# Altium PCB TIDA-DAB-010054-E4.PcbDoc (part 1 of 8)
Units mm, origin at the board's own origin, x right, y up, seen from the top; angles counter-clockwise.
Board outline 300 x 180 mm, 4 copper layers (Top Layer, Inner Layer1, Inner Layer2, Bottom Layer), stack 1.605 mm thick; 873 components, 388 nets, 2405 pads, 1542 vias.
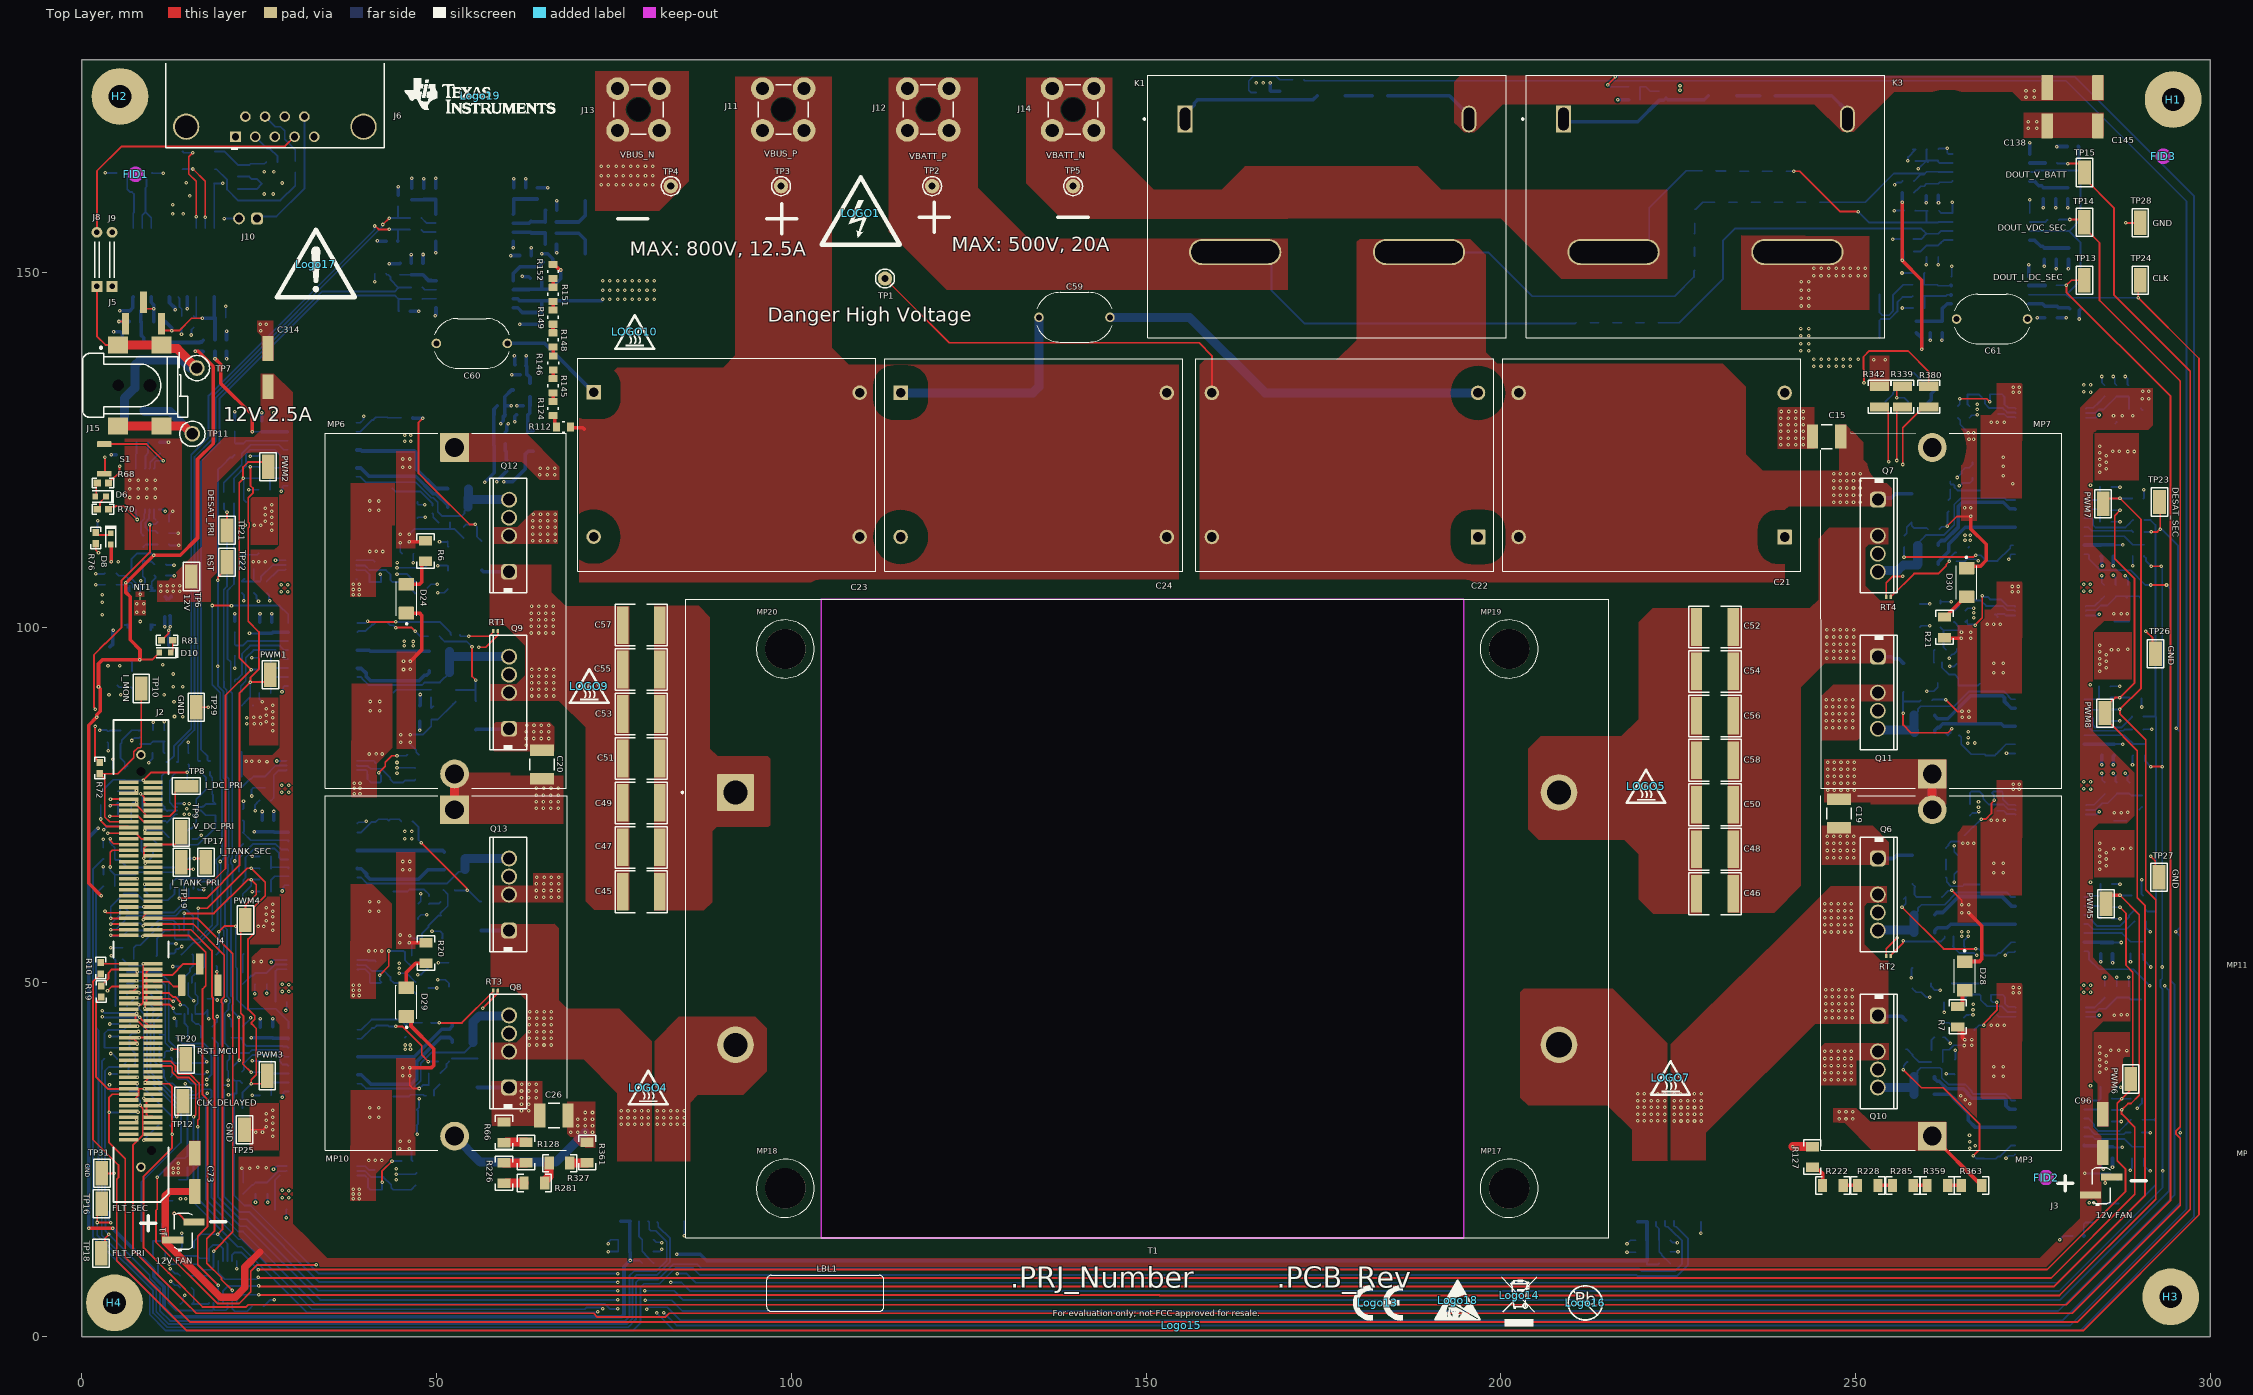
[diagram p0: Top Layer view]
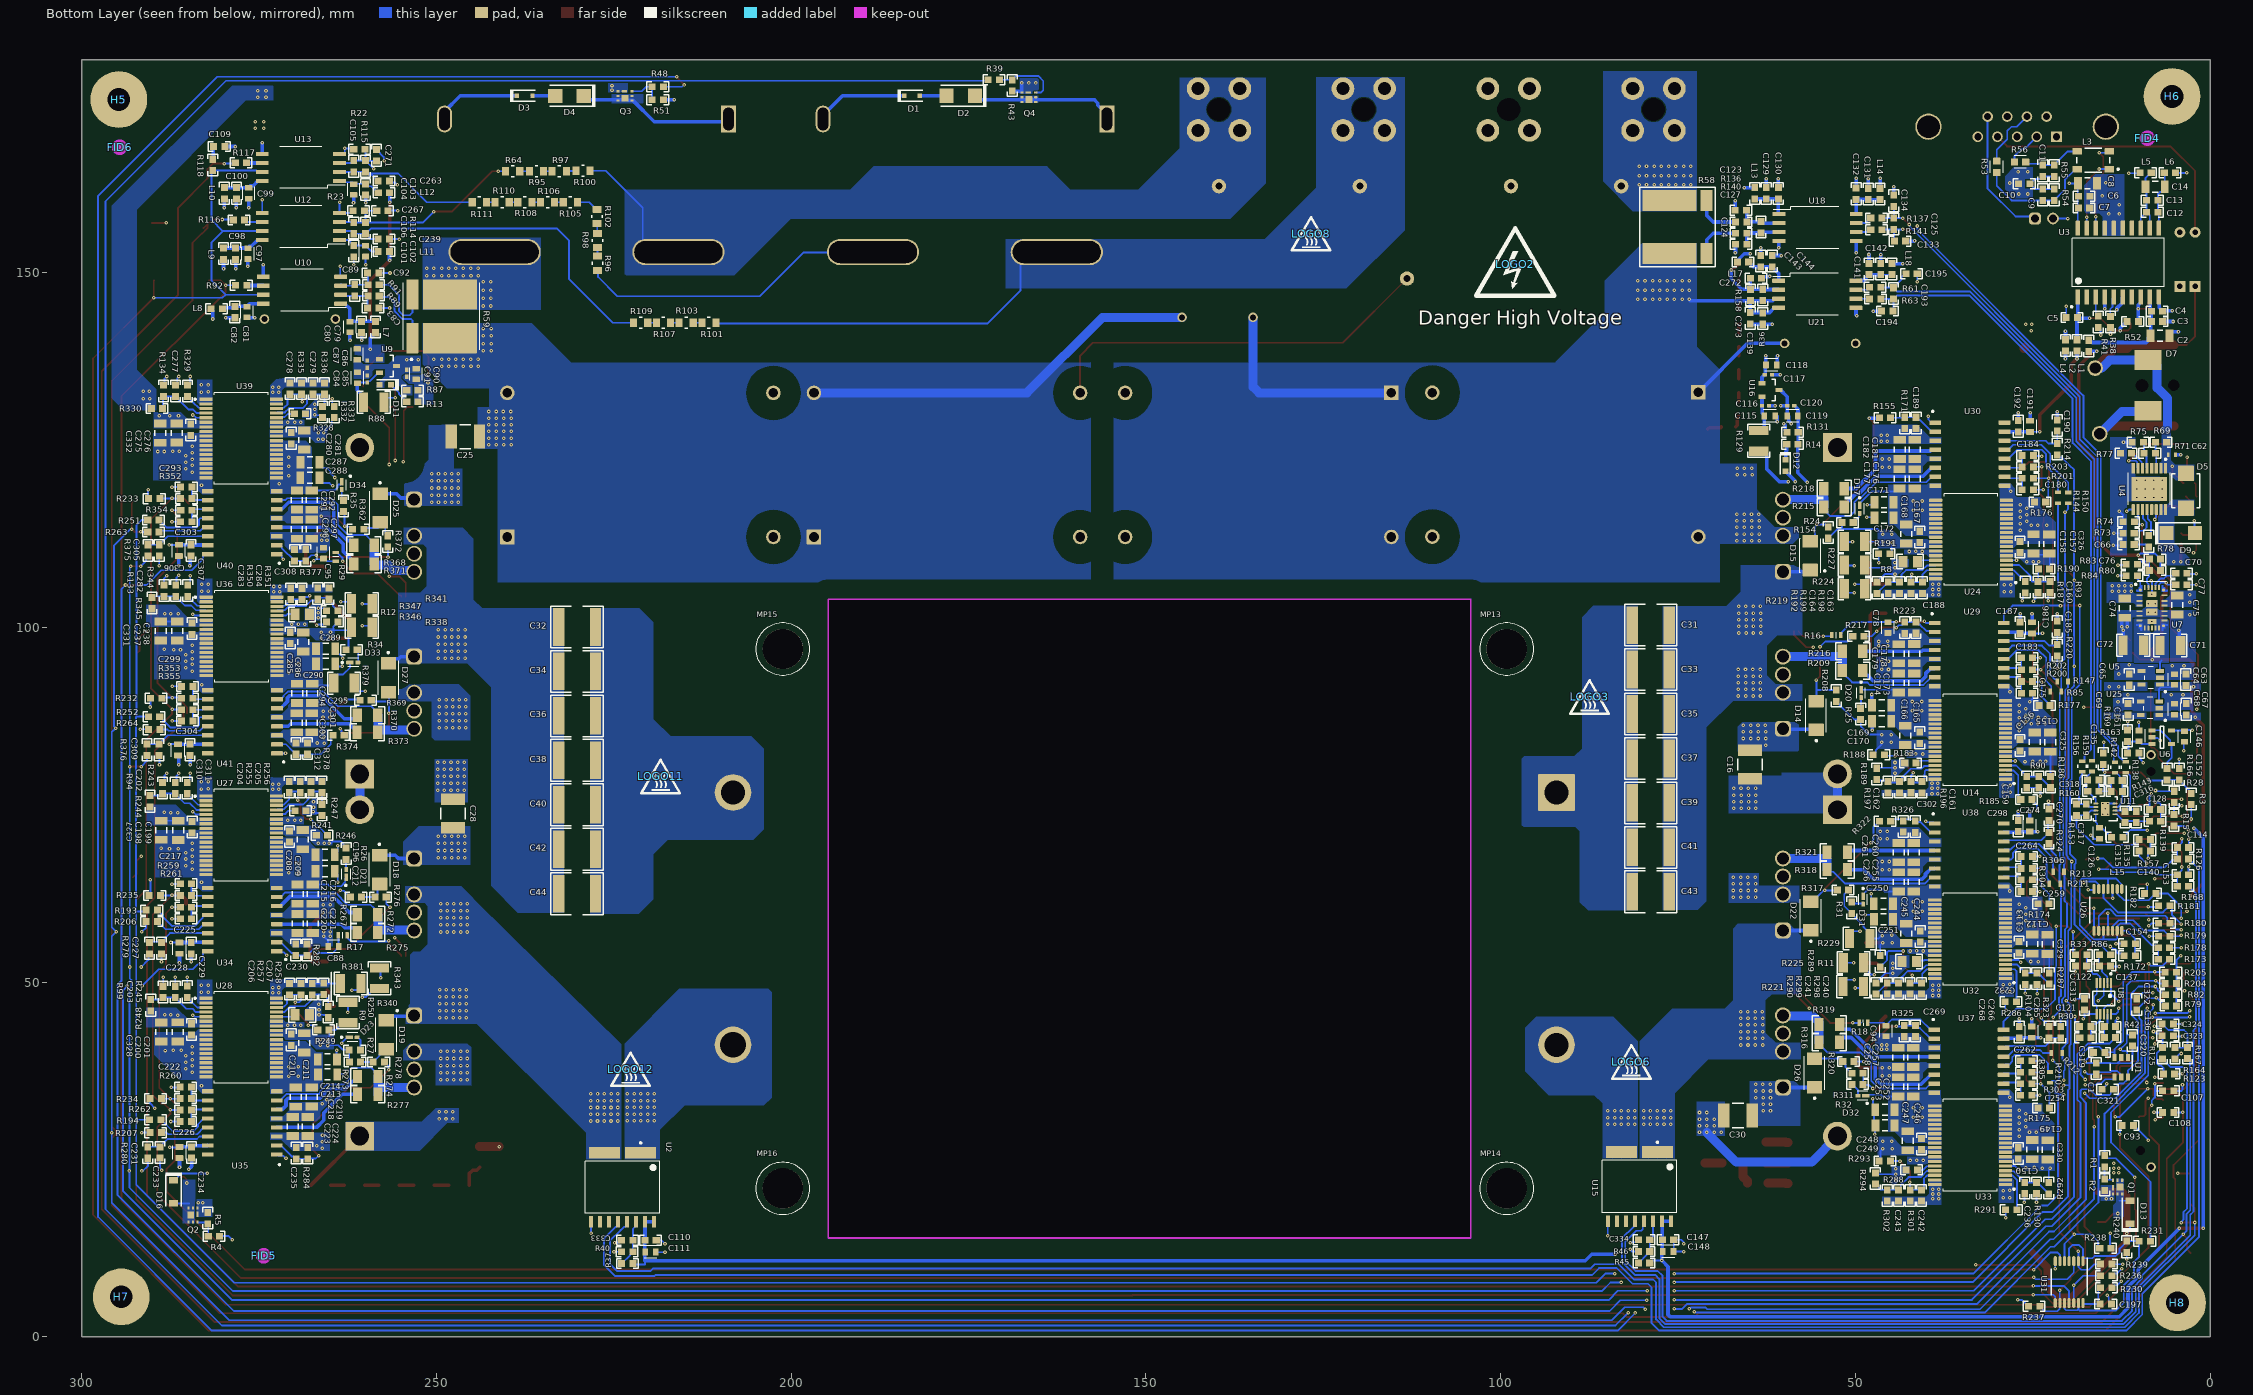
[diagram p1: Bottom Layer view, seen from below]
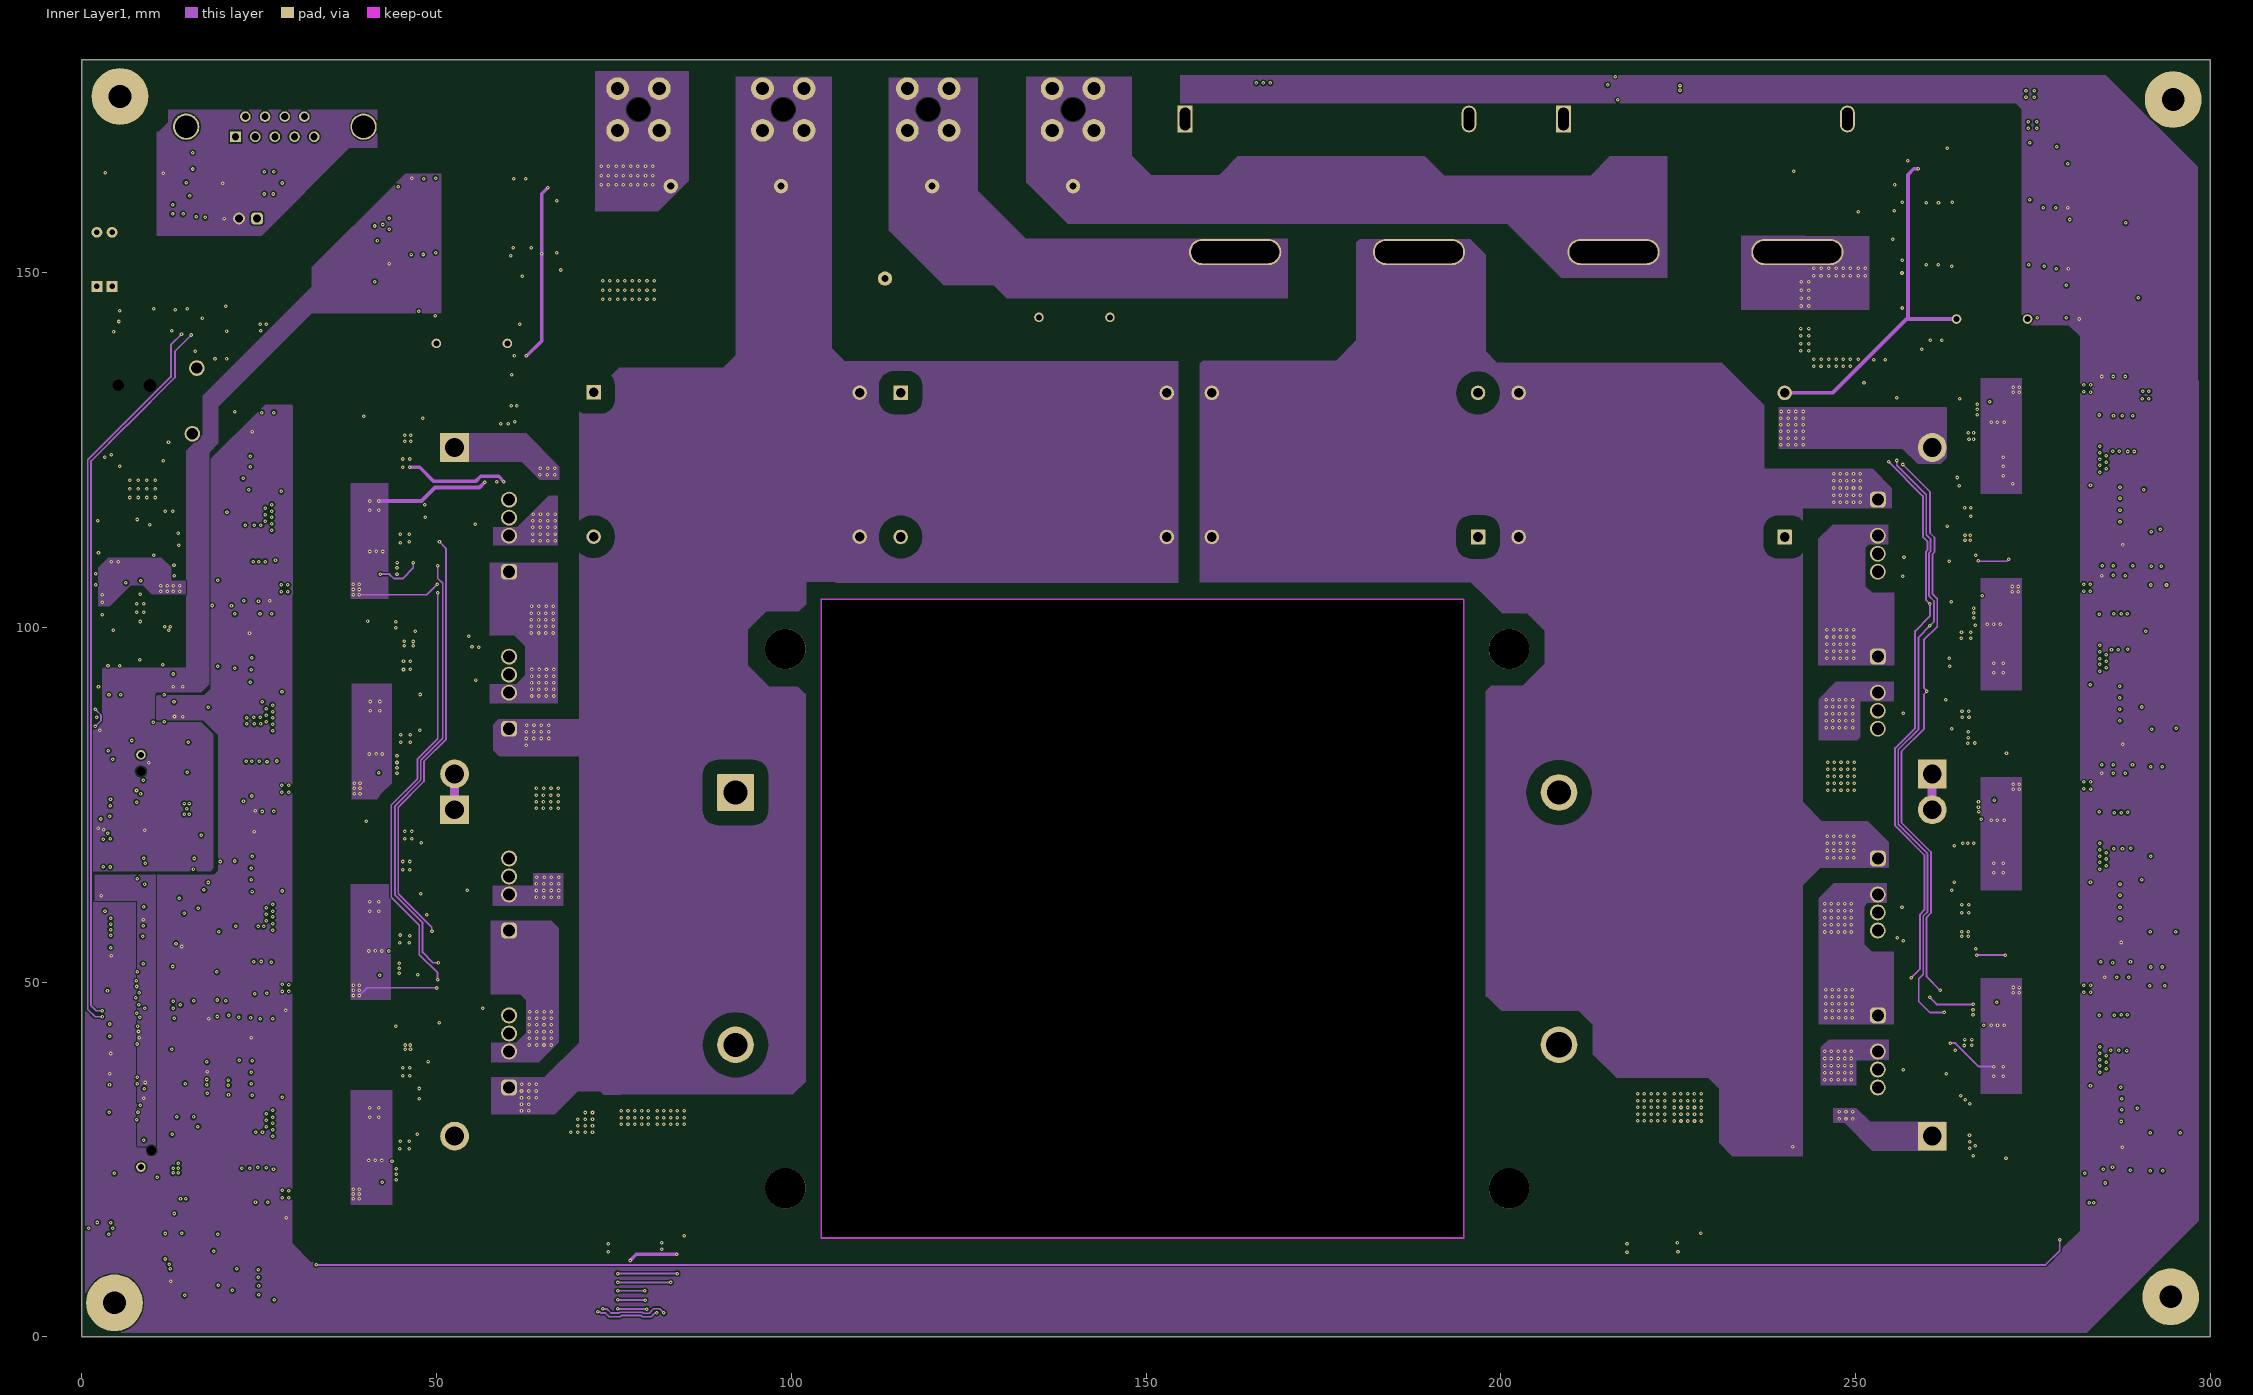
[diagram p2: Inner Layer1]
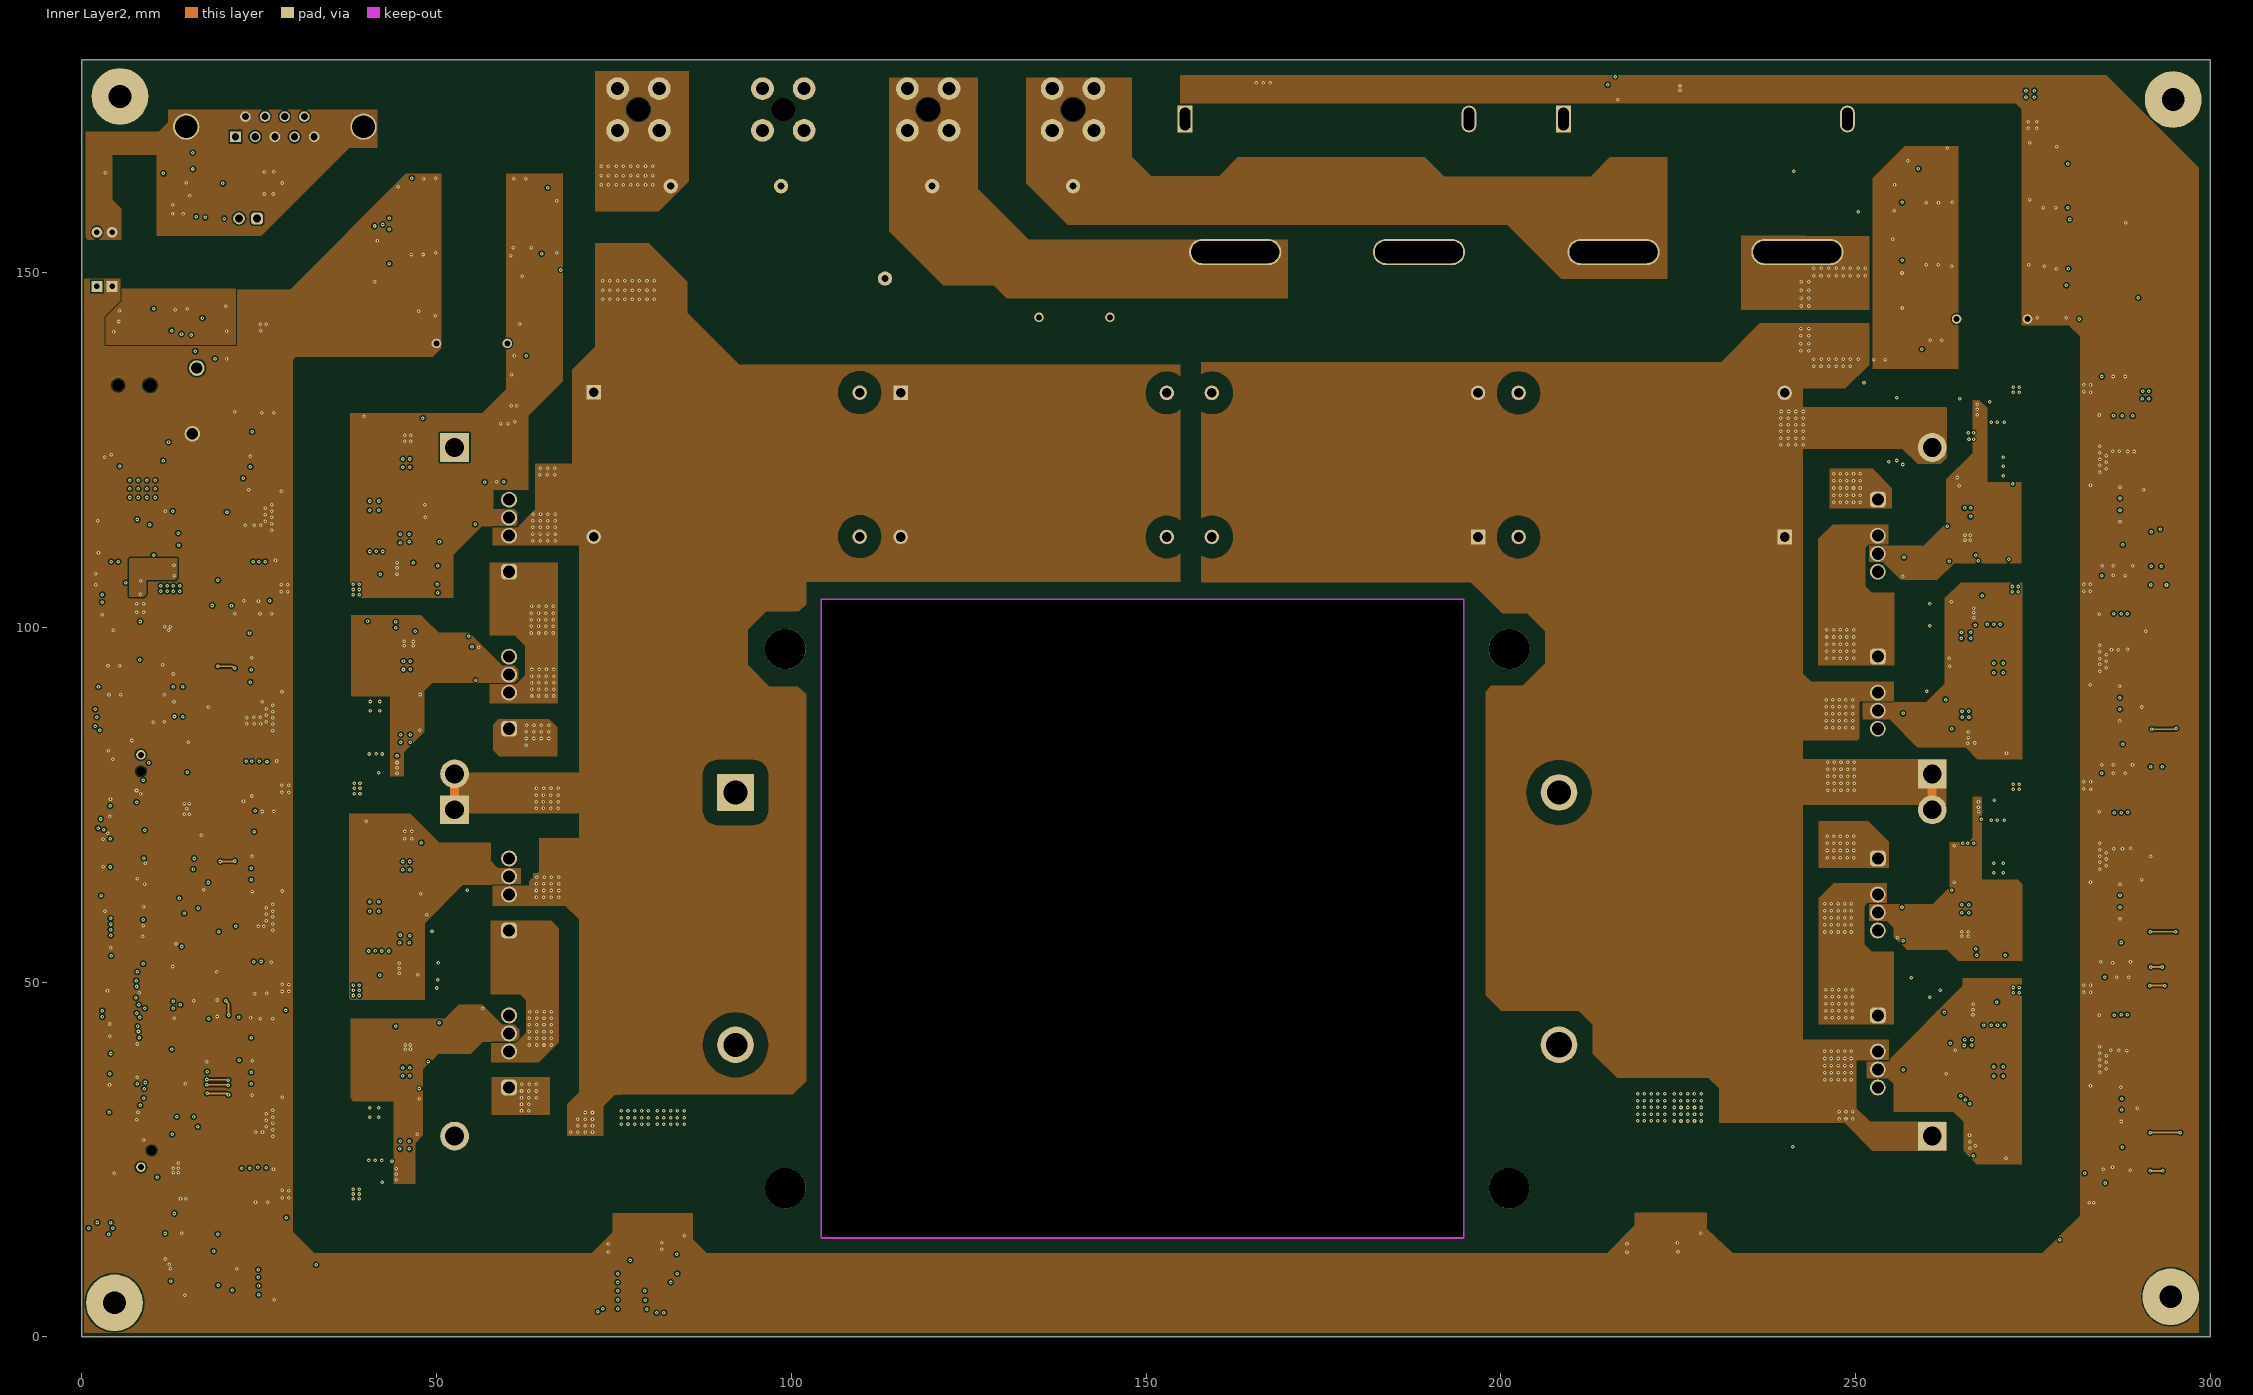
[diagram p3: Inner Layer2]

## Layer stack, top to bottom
Top Solder: solder mask 0.0102, Solder Resist, Dk 3.5
Top Layer: signal copper 0.0711
Dielectric 2: dielectric 0.3048, FR-4 High Tq, Dk 4.2
Inner Layer1: signal copper 0.0711
Dielectric1: core 0.7112, FR-4 High Tq, Dk 4.8
Inner Layer2: signal copper 0.0711
Dielectric 5: dielectric 0.3048, FR-4 High Tq, Dk 4.2
Bottom Layer: signal copper 0.0711
Bottom Solder: solder mask 0.0102, Solder Resist, Dk 3.5

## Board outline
0,0 300,0 300,180 0,180
cut-out: 194.784,103.944 194.784,13.944 104.245,13.944 104.245,103.944

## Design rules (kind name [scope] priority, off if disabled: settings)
AcuteAngle [All] p1: minimum=4.50000000000000E+0001 checktracksonly=FALSE
AssemblyTestPointUsage [All] p1: valid=2
BoardOutlineClearance BoardOutlineClearance_MountingHoles [OnCopper and InComponentClass('Mounting Holes')] p1: gap=0 ignorepadtopadclearanceinfootprint=FALSE
BoardOutlineClearance BoardOutlineClearance_Poly [OnCopper and IsPoly] p2: gap=0 ignorepadtopadclearanceinfootprint=FALSE
BoardOutlineClearance [OnCopper and Not InComponentClass('Logo') and not InComponentClass('FiducialMark') and not InRegion(1100,1300,4500,1600) and not InPoly] p3: gap=0.762 ignorepadtopadclearanceinfootprint=FALSE
Clearance ClearanceFiducail [InComponentClass('FiducialMark')] p1: gap=0 ignorepadtopadclearanceinfootprint=TRUE
Clearance Clearance_6 [InNetClass('HV_BAT_N') vs InNet('NetR97_2')] p2: gap=0.5 ignorepadtopadclearanceinfootprint=TRUE
Clearance Clearance_7 [InNetClass('HV_BAT_P') vs InNet('NetR101_1')] p3: gap=0.5 ignorepadtopadclearanceinfootprint=TRUE
Clearance Clearance_5 [InNetClass('HV') vs InNet('NetC139_1')] p4: gap=0.5 ignorepadtopadclearanceinfootprint=TRUE
Clearance Clearance_4 [InNetClass('HV_P_N') vs InNet('NetR151_1')] p5: gap=0.5 ignorepadtopadclearanceinfootprint=TRUE
Clearance Clearance_3 [InNet('D1H_S') OR InNet('SGND') vs InNet('MPS')] p6: gap=1.5 ignorepadtopadclearanceinfootprint=TRUE
Clearance Clearance_2 [InNet('SGND') vs InNet('NetR359_1')] p7: gap=0.5 ignorepadtopadclearanceinfootprint=TRUE
Clearance Clearance_1 [InNet('D1H_S') vs InNet('NetR127_1')] p8: gap=0.5 ignorepadtopadclearanceinfootprint=TRUE
Clearance Clearance_MidPoint_VS [InNet('D1H_P') vs InNet('NetR66_1') OR inNet('MPP') OR InNet('NetR112_2')] p9: gap=1 ignorepadtopadclearanceinfootprint=TRUE
Clearance Clearance_MidPoint_1 [InNet('PGND') vs InNet('NetR327_1') OR inNet('MPP')] p10: gap=1.5 ignorepadtopadclearanceinfootprint=TRUE
Clearance Clearance_Keep_out [OnLayer('Keep-Out Layer')] p11: gap=0 ignorepadtopadclearanceinfootprint=TRUE
Clearance Clearance_VoltageSensing1 [InNet('D1H_S') vs InNet('NetR96_1')] p12: gap=0.5 ignorepadtopadclearanceinfootprint=TRUE
Clearance Clearance_VoltageSensing2 [InNet('NetC106_1') vs InNet('NetR107_2')] p13: gap=0.5 ignorepadtopadclearanceinfootprint=TRUE
Clearance Clearance_VoltageSensing3 [InNet('NetC105_1') vs InNet('NetR110_2')] p14: gap=0.5 ignorepadtopadclearanceinfootprint=TRUE
Clearance Clearance_VoltageSensing3_1 [InNet('NetC106_2') vs InNet('NetR64_1')] p15: gap=0.5 ignorepadtopadclearanceinfootprint=TRUE
Clearance Clearance_Pad_in_Connector [IsPad AND InComponent('J11','J12','J13','J14')] p16: gap=0.1 ignorepadtopadclearanceinfootprint=TRUE
Clearance Clearance_T1 [IsBoardCutoutRegion OR InComponentClass('T1') vs (OnLayer('Top Layer') OR OnLayer('Bottom Layer') OR OnLayer('Multi-Layer'))] p17: gap=2.8 ignorepadtopadclearanceinfootprint=TRUE
Clearance Clearance_T1_1 [IsBoardCutoutRegion OR InComponentClass('T1') vs NOT(OnLayer('Top Layer') OR OnLayer('Bottom Layer') OR OnLayer('Multi-Layer'))] p18: gap=2 ignorepadtopadclearanceinfootprint=TRUE
Clearance Clearance_HV_TO_LV_ext [(InNetClass('HV_P_H') OR InNetClass('HV_P_N') OR InNetClass('HV') OR InNetClass('HV_P_SW1') OR InNetClass('HV_P_SW2') OR InNetClass('HV_S_N')OR InNetClass('HV_S_P') OR InNetClass('HV_S_SW1') OR InNetClass('HV_S_SW2') OR InNetClass('HV_BAT_P') OR InNetClass('HV_BAT_N'))AND (OnLayer('Bottom Layer') OR OnLayer('Top Layer')OR OnLayer('Multi-Layer')) vs NOT(InNetClass('HV_P_H') OR InNetClass('HV_P_N') OR InNetClass('HV') OR InNetClass('HV_P_SW1') OR InNetClass('HV_P_SW2') OR InNetClass('HV_S_N')OR InNetClass('HV_S_P') OR InNetClass('HV_S_SW1') OR InNetClass('HV_S_SW2') OR InNetClass('HV_BAT_P') OR InNetClass('HV_BAT_N'))  AND (OnLayer('Bottom Layer') OR OnLayer('Top Layer')OR OnLayer('Multi-Layer'))] p19: gap=8 ignorepadtopadclearanceinfootprint=TRUE
Clearance Clearance_HV_TO_LV_int [(InNetClass('HV_P_H') OR InNetClass('HV_P_N') OR InNetClass('HV') OR InNetClass('HV_P_SW1') OR InNetClass('HV_P_SW2') OR InNetClass('HV_S_N')OR InNetClass('HV_S_P') OR InNetClass('HV_S_SW1') OR InNetClass('HV_S_SW2') OR InNetClass('HV_BAT_P') OR InNetClass('HV_BAT_N')) AND NOT(OnLayer('Bottom Layer') OR OnLayer('Top Layer')OR OnLayer('Multi-Layer')) vs NOT(InNetClass('HV_P_H') OR InNetClass('HV_P_N') OR InNetClass('HV') OR InNetClass('HV_P_SW1') OR InNetClass('HV_P_SW2') OR InNetClass('HV_S_N')OR InNetClass('HV_S_P') OR InNetClass('HV_S_SW1') OR InNetClass('HV_S_SW2') OR InNetClass('HV_BAT_P') OR InNetClass('HV_BAT_N')) AND NOT(OnLayer('Bottom Layer') OR OnLayer('Top Layer'))] p20: gap=6 ignorepadtopadclearanceinfootprint=TRUE
Clearance Clearance_HV1_ext [InNetClass('HV_P_SW1') AND(OnLayer('Bottom Layer') OR OnLayer('Top Layer')OR OnLayer('Multi-Layer')) vs NOT InNetClass('HV_P_SW1') AND(OnLayer('Bottom Layer') OR OnLayer('Top Layer')OR OnLayer('Multi-Layer'))] p21: gap=2.8 ignorepadtopadclearanceinfootprint=TRUE
Clearance Clearance_HV1_int [InNetClass('HV_P_SW1') vs NOT InNetClass('HV_P_SW1')] p22: gap=2 ignorepadtopadclearanceinfootprint=TRUE
Clearance Clearance_HV10_ext [InNetClass('HV_BAT_P') AND(OnLayer('Bottom Layer') OR OnLayer('Top Layer')OR OnLayer('Multi-Layer')) vs NOT InNetClass('HV_BAT_P') AND(OnLayer('Bottom Layer') OR OnLayer('Top Layer')OR OnLayer('Multi-Layer'))] p23: gap=2.8 ignorepadtopadclearanceinfootprint=TRUE
Clearance Clearance_HV10_int [InNetClass('HV_BAT_P') vs NOT InNetClass('HV_BAT_P')] p24: gap=2 ignorepadtopadclearanceinfootprint=TRUE
Clearance Clearance_HV11_ext [InNetClass('HV_BAT_N') AND(OnLayer('Bottom Layer') OR OnLayer('Top Layer')OR OnLayer('Multi-Layer')) vs NOT InNetClass('HV_BAT_N') AND(OnLayer('Bottom Layer') OR OnLayer('Top Layer')OR OnLayer('Multi-Layer'))] p25: gap=2.8 ignorepadtopadclearanceinfootprint=TRUE
Clearance Clearance_HV11_int [InNetClass('HV_BAT_N') vs NOT InNetClass('HV_BAT_N')] p26: gap=2 ignorepadtopadclearanceinfootprint=TRUE
Clearance Clearance_HV2_ext [InNetClass('HV')AND(OnLayer('Bottom Layer') OR OnLayer('Top Layer')OR OnLayer('Multi-Layer')) vs NOT InNetClass('HV') AND (OnLayer('Bottom Layer') OR OnLayer('Top Layer')OR OnLayer('Multi-Layer'))] p27: gap=2.8 ignorepadtopadclearanceinfootprint=TRUE
Clearance Clearance_HV2_int [InNetClass('HV') vs NOT InNetClass('HV')] p28: gap=2 ignorepadtopadclearanceinfootprint=TRUE
Clearance Clearance_HV3_ext [InNetClass('HV_P_H')AND(OnLayer('Bottom Layer') OR OnLayer('Top Layer')OR OnLayer('Multi-Layer')) vs NOT InNetClass('HV_P_H')AND(OnLayer('Bottom Layer') OR OnLayer('Top Layer')OR OnLayer('Multi-Layer'))] p29: gap=2.8 ignorepadtopadclearanceinfootprint=TRUE
Clearance Clearance_HV3_int [InNetClass('HV_P_H') vs NOT InNetClass('HV_P_H')] p30: gap=2 ignorepadtopadclearanceinfootprint=TRUE
Clearance Clearance_HV4_ext [InNetClass('HV_P_N')AND(OnLayer('Bottom Layer') OR OnLayer('Top Layer')OR OnLayer('Multi-Layer')) vs NOT InNetClass('HV_P_N')AND(OnLayer('Bottom Layer') OR OnLayer('Top Layer')OR OnLayer('Multi-Layer'))] p31: gap=2.8 ignorepadtopadclearanceinfootprint=TRUE
Clearance Clearance_HV4_int [InNetClass('HV_P_N') vs NOT InNetClass('HV_P_N')] p32: gap=2 ignorepadtopadclearanceinfootprint=TRUE
Clearance Clearance_HV5_ext [InNetClass('HV_P_SW2')AND(OnLayer('Bottom Layer') OR OnLayer('Top Layer')OR OnLayer('Multi-Layer')) vs NOT InNetClass('HV_P_SW2')AND(OnLayer('Bottom Layer') OR OnLayer('Top Layer')OR OnLayer('Multi-Layer'))] p33: gap=2.8 ignorepadtopadclearanceinfootprint=TRUE
Clearance Clearance_HV5_int [InNetClass('HV_P_SW2') vs NOT InNetClass('HV_P_SW2')] p34: gap=2 ignorepadtopadclearanceinfootprint=TRUE
Clearance Clearance_HV6_ext [InNetClass('HV_S_N')AND(OnLayer('Bottom Layer')OR OnLayer('Top Layer')OR OnLayer('Multi-Layer')) vs NOT InNetClass('HV_S_N')AND(OnLayer('Bottom Layer') OR OnLayer('Top Layer')OR OnLayer('Multi-Layer'))] p35: gap=2.8 ignorepadtopadclearanceinfootprint=TRUE
Clearance Clearance_HV6_int [InNetClass('HV_S_N') vs NOT InNetClass('HV_S_N')] p36: gap=2 ignorepadtopadclearanceinfootprint=TRUE
Clearance Clearance_HV7_ext [InNetClass('HV_S_P')AND(OnLayer('Bottom Layer') OR OnLayer('Top Layer')OR OnLayer('Multi-Layer')) vs NOT InNetClass('HV_S_P') AND(OnLayer('Bottom Layer') OR OnLayer('Top Layer')OR OnLayer('Multi-Layer'))] p37: gap=2.8 ignorepadtopadclearanceinfootprint=TRUE
Clearance Clearance_HV7_int [InNetClass('HV_S_P') vs NOT InNetClass('HV_S_P')] p38: gap=2 ignorepadtopadclearanceinfootprint=TRUE
Clearance Clearance_HV8_ext [InNetClass('HV_S_SW1') AND(OnLayer('Bottom Layer') OR OnLayer('Top Layer')OR OnLayer('Multi-Layer')) vs NOT InNetClass('HV_S_SW1')  AND(OnLayer('Bottom Layer') OR OnLayer('Top Layer')OR OnLayer('Multi-Layer'))] p39: gap=2.8 ignorepadtopadclearanceinfootprint=TRUE
Clearance Clearance_HV8_int [InNetClass('HV_S_SW1') vs NOT InNetClass('HV_S_SW1')] p40: gap=2 ignorepadtopadclearanceinfootprint=TRUE
Clearance Clearance_HV9_ext [InNetClass('HV_S_SW2')AND(OnLayer('Bottom Layer') OR OnLayer('Top Layer')OR OnLayer('Multi-Layer')) vs NOT InNetClass('HV_S_SW2') AND(OnLayer('Bottom Layer') OR OnLayer('Top Layer')OR OnLayer('Multi-Layer'))] p41: gap=2.8 ignorepadtopadclearanceinfootprint=TRUE
Clearance Clearance_HV9_int [InNetClass('HV_S_SW2') vs NOT InNetClass('HV_S_SW2')] p42: gap=2 ignorepadtopadclearanceinfootprint=TRUE
Clearance [All] p43: gap=0.203 ignorepadtopadclearanceinfootprint=TRUE
ComponentClearance "SCREWS T1" [InComponentClass('T1') vs InComponentClass('T1')] p1: gap=0 collisioncheckmode=3 verticalgap=0 showdistances=FALSE
ComponentClearance "HEAT SINK" [InComponent('Q*') vs InComponent('MP*')] p2: gap=0 collisioncheckmode=3 verticalgap=0 showdistances=FALSE
ComponentClearance ComponentClearance_MountingHoles_FiducialMarks [InComponentClass('Mounting Holes') vs InComponentClass('FiducialMark')] p3: gap=0.254 collisioncheckmode=3 verticalgap=0.254 showdistances=FALSE
ComponentClearance ComponentClearance_Shunt [InComponentClass('Header') vs InComponentClass('Shunt')] p4: gap=0 collisioncheckmode=3 verticalgap=0 showdistances=FALSE
ComponentClearance ComponentClearance_Logo [InComponentClass('Logo')] p5: gap=0.254 collisioncheckmode=3 verticalgap=0.254 showdistances=FALSE
ComponentClearance ComponentClearance_ScrewToNut [(HasFootprint('NY PMS 440 0025 PH')) vs (HasFootprint('Keystone_1902C'))] p6: gap=0.127 collisioncheckmode=3 verticalgap=0.254 showdistances=FALSE
ComponentClearance ComponentClearance_ScrewToNut_1 [(HasFootprint('FP-PMSSS 832 0063 PH_SCREW_0IN322_MFG')) vs (HasFootprint('FP-1474C_HEX_STANDOFF_8-32_1IN2_MFG'))] p7: gap=0.127 collisioncheckmode=3 verticalgap=0.254 showdistances=FALSE
ComponentClearance ComponentClearance_MountingHoles [InComponentClass('Mounting Holes')] p8: gap=0.254 collisioncheckmode=3 verticalgap=2540 showdistances=FALSE
ComponentClearance ComponentClearance_SmallPassives [HasFootprint('0201*') or HasFootprint('0402*') or HasFootprint('0508') or HasFootprint('0603*') or HasFootprint('0612') or HasFootprint('0805*') or HasFootprint('0815*') or HasFootprint('0830*') or HasFootprint('1206*') or HasFootprint('1210*') or HasFootprint('1808*') or HasFootprint('1812*') or HasFootprint('1825*') or HasFootprint('2010*') or HasFootprint('2220*') or HasFootprint('2225*') or HasFootprint('2512*') or HasFootprint('2728*') or HasFootprint('3518*') vs HasFootprint('0201*') or HasFootprint('0402*') or HasFootprint('0508') or HasFootprint('0603*') or HasFootprint('0612') or HasFootprint('0805*') or HasFootprint('0815*') or HasFootprint('0830*') or HasFootprint('1206*') or HasFootprint('1210*') or HasFootprint('1808*') or HasFootprint('1812*') or HasFootprint('1825*') or HasFootprint('2010*') or HasFootprint('2220*') or HasFootprint('2225*') or HasFootprint('2512*') or HasFootprint('2728*') or HasFootprint('3518*')] p9: gap=0.254 collisioncheckmode=3 verticalgap=0.254 showdistances=FALSE
ComponentClearance ComponentClearance_THtoSMT [IsThruComponent vs IsSMTComponent] p10: gap=0.254 collisioncheckmode=3 verticalgap=0.254 showdistances=FALSE
ComponentClearance ComponentClearance_THtoTH [IsThruComponent vs IsThruComponent] p11: gap=0.254 collisioncheckmode=3 verticalgap=0.254 showdistances=FALSE
ComponentClearance [All] p12: gap=0.254 collisioncheckmode=3 verticalgap=0.254 showdistances=FALSE
DiffPairsRouting [All] p1: maxlimit=2.54 minlimit=0.254 mostfreqgap=0.381 toplayer_minwidth=0.254 toplayer_maxwidth=0.381 toplayer_prefwidth=0.381 midlayer1_minwidth=0.254 midlayer1_maxwidth=0.381 midlayer1_prefwidth=0.381 midlayer3_prefgap=0.254 midlayer3_minwidth=0.254 midlayer3_maxwidth=2.54 midlayer3_prefwidth=0.254 bottomlayer_minwidth=0.254 bottomlayer_maxwidth=0.381 bottomlayer_prefwidth=0.381 maxuncoupledlength=25.4
FabricationTestPointUsage TestPointUsage [All] p1: valid=2 allowmultiple=FALSE
FabricationTestpoint Testpoint [All] p1: side=3 testpointundercomponent=TRUE minsize=1.016 maxsize=2.54 preferedsize=1.524 minholesize=0 maxholesize=1.016 preferedholesize=0.813 testpointgrid=0.025 allowsidetop=TRUE allowsidebottom=TRUE usegrid=TRUE gridtolerance=0
FanoutControl Fanout_LCC [IsLCC] p1: bgadir=Out bgaviamode=Centered fanoutstyle=Auto fanoutdirection=Alternating viagrid=0.025 // Fanout_LCC (Default Rule)
FanoutControl Fanout_BGA [IsBGA] p2: bgadir=Out bgaviamode=Centered fanoutstyle=Auto fanoutdirection=Alternating viagrid=0.025 // Fanout_BGA (Default Rule)
Height [All] p1: minheight=0 maxheight=63.5 prefheight=12.7
HoleSize [All] p1: absolutevalues=TRUE maxlimit=15 minlimit=0.2 maxpercent=80.000 minpercent=20.000
HoleToHoleClearance HoleToHoleClearanceT1 [InComponentClass('T1') vs InComponentClass('T1')] p1: gap=0 allowstackedmicrovias=FALSE
HoleToHoleClearance [All] p2: gap=0.254 allowstackedmicrovias=TRUE
MinimumAnnularRing MinimumAnnularRing_ThermalPadVias [IsVia and InAnyComponent] p1: minimumring=0.15
MinimumAnnularRing [All] p2: minimumring=0.15
MinimumSolderMaskSliver MinimumSolderMaskSliver_Logo [InComponentClass('Logo') vs InComponentClass('Logo')] p1: minsoldermaskwidth=0.018
MinimumSolderMaskSliver [All] p2: minsoldermaskwidth=0.1
PlaneConnect [All] p1: planeconnectstyle=Direct reliefexpansion=0.254 reliefentries=4 reliefconductorwidth=0.254 reliefairgap=0.254
PolygonConnect [All] p1: connectstyle=Direct reliefconductorwidth=0.254 reliefentries=4 polygonreliefangle="90 Angle" airgapwidth=0.254
RoutingVias ThermalPadVias [IsVia and InAnyComponent] p1: holewidth=0.2 width=0.5 viastyle="Through Hole" minholewidth=0.2 minwidth=0.5 maxholewidth=15 maxwidth=0.6
RoutingVias [All] p2: holewidth=0.406 width=0.864 viastyle="Through Hole" minholewidth=0.406 minwidth=0.864 maxholewidth=2.54 maxwidth=2.54 useviatemplates=TRUE viatemplateguid#1={90AF9DCA-38FE-492F-8745-FEBA7A06F245} viatemplatename#1=v50h20m0mx0
ShortCircuit [InComponentClass('T1') vs InComponentClass('T1')] p1: allowed=TRUE
SilkToSilkClearance SilkToSilkClearance_Pb-FreeLogo [(HasFootprint('Pb-Free_Overlay_Medium') OR HasFootprint('Pb-Free_Overlay_Small')) vs (HasFootprint('Pb-Free_Overlay_Medium') OR HasFootprint('Pb-Free_Overlay_Small'))] p1: silktosilkclearance=0
SilkToSilkClearance [All] p2: silktosilkclearance=0.1
SilkToSolderMaskClearance SilkToComponentPadClearance [(IsPad or IsFill or IsRegion) and InAnycomponent] p1: minsilkscreentomaskgap=0.09 clearancetoexposedcopper=TRUE
SilkToSolderMaskClearance "Silk to Solder Mask Opening" [All] p2: minsilkscreentomaskgap=0.1 clearancetoexposedcopper=FALSE
SolderMaskExpansion [All] p1: expansion=0.05 istentingtop=FALSE
UnConnectedPin [All] p1:
Width [All] p1: maxlimit=1.27 minlimit=0.127 preferedwidth=0.254 checkconnectedcopper=TRUE
15 further rules are at their usual default settings.

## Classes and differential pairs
component class Logo: Logo19
net class HV_BAT_P: VBATT_P
net class HV_BAT_N: VBATT_N
component class T1: MP13 MP14 MP15 MP16 MP17 MP18 MP19 MP20 T1
net class HV_S_SW2: +15V_TOP4 -4V_TOP4 D2L_S G2H_S NetC32_2 NetC95_2 NetC278_1 NetC279_1 NetC308_1 NetD25_2 NetD34_2 NetR29_2 NetR328_1 NetR368_1 NetR371_1 S2H_S
net class HV_S_SW1: +15V_TOP3 -4V_TOP3 D1L_S G1H_S I_SEC_P NetC88_2 NetC204_1 NetC205_1 NetC230_1 NetD18_2 NetD21_2 NetR17_2 NetR241_1 NetR272_1 NetR275_1 S1H_S
net class HV_S_P: D1H_S
net class HV_S_N: 5V_ISO_S +15V_BOT3 +15V_BOT4 +15V_SEN_SEC -4V_BOT3 -4V_BOT4 -4V_SEN_SEC G1L_S G2L_S GND_SEN_SEC I_OUT_N I_OUT_P NetC79_1 NetC83_2 NetC84_1 NetC89_2 NetC101_1 NetC103_1 NetC105_1 NetC106_1 NetC106_2 NetC206_1 NetC207_1 NetC235_1 NetC283_1 NetC284_1 NetC312_1 NetD11_1 NetD19_2 NetD23_2 NetD27_2 NetD28_2 NetD30_2 NetD33_2 NetK3_4 NetR9_1 NetR12_1 NetR274_1 NetR277_1 NetR338_2 NetR341_2 NetR370_1 NetR373_1 NetR379_2 S1L_S S2L_S SGND
net class HV_P_SW2: +15V_TOP2 -4V_TOP2 D2L_P G2H_P I_PRI_P NetC94_2 NetC242_1 NetC243_1 NetC269_1 NetD26_2 NetD32_2 NetR18_2 NetR288_1 NetR316_1 NetR319_1 S2H_P
net class HV_P_SW1: +15V_TOP1 -4V_TOP1 D1L_P G1H_P NetC31_1 NetC78_2 NetC161_1 NetC162_1 NetC188_1 NetD14_2 NetD20_2 NetR16_2 NetR183_1 NetR209_1 NetR216_1 S1H_P
net class HV_P_N: 5V_ISO_P +15V_BOT1 +15V_BOT2 -4V_BOT1 -4V_BOT2 G1L_P G2L_P Iin+ Iin- NetC115_1 NetC123_2 NetC124_2 NetC129_1 NetC139_1 NetC143_1 NetC163_1 NetC164_1 NetC189_1 NetC240_1 NetC241_1 NetC302_1 NetD12_1 NetD15_2 NetD17_2 NetD22_2 NetD24_2 NetD29_2 NetD31_2 NetR8_1 NetR11_1 NetR215_1 NetR218_1 NetR219_2 NetR224_2 NetR227_2 NetR318_1 NetR321_1 PGND S1L_P S2L_P VBUS_N
net class HV_P_H: D1H_P
component class TIDA-DAB-010054-E4_PrimarySideSensing: C115 C116 C117 C118 C119 C120 C123 C124 C125 C126 C127 C128 C129 C130 C131 C132 C133 C134 C135 C139 C140 C141 C142 C143 C144 C146 C147 C148 C151 C152 C153 C193 C194 C195 C272 C273 C315 C316 C317 C318 C324 C334 D12 L13 L14 L15 L17 L18 R14 R36 R45 R46 R61 R63 R112 R124 R129 R131 R135 R136 R137 R138 R139 R140 R141 R142 R143 R145 R146 R148 R149 R151 R152 R153 R156 R157 R158 R159 R160 R163 R164 R166 R167 R168 R169 TP8 TP9 TP18 TP19 TP31 U11 U15 U16 U18 U21 U25
component class TIDA-DAB-010054-E4_GateDriverSecHB2: C95 C237 C238 C275 C276 C277 C278 C279 C280 C281 C282 C283 C284 C285 C286 C287 C288 C289 C290 C291 C292 C293 C294 C295 C296 C297 C299 C300 C301 C303 C304 C305 C306 C307 C308 C309 C310 C311 C312 C331 C332 D25 D27 D30 D33 D34 R12 R21 R29 R34 R35 R133 R134 R251 R252 R263 R264 R328 R329 R330 R331 R332 R335 R336 R344 R345 R346 R347 R350 R351 R352 R353 R354 R355 R362 R368 R369 R370 R371 R372 R373 R374 R375 R376 R377 R378 RT4 U36 U39 U40 U41
component class TIDA-DAB-010054-E4_GateDriverSecHB1: C88 C196 C197 C198 C199 C200 C201 C202 C203 C204 C205 C206 C207 C208 C209 C210 C211 C212 C213 C214 C215 C216 C217 C218 C219 C220 C221 C222 C223 C224 C225 C226 C227 C228 C229 C230 C231 C233 C234 C235 C327 C328 D18 D19 D21 D23 D28 PWM5 PWM6 PWM7 PWM8 R7 R9 R17 R26 R27 R94 R99 R193 R194 R206 R207 R230 R231 R232 R233 R234 R235 R236 R237 R238 R239 R240 R241 R243 R244 R245 R246 R247 R248 R249 R250 R255 R256 R257 R258 R259 R260 R261 R262 R267 R272 R273 R274 R275 R276 R277 R278 R279 R280 R282 R284 R338 R339 R340 R341 R342 R343 R379 R380 R381 RT2 U27 U28 U31 U34 U35
component class TIDA-DAB-010054-E4_GateDriverPrimHB2: C94 C112 C113 C149 C150 C232 C236 C240 C241 C242 C243 C244 C245 C246 C247 C248 C249 C250 C251 C252 C253 C254 C255 C256 C257 C258 C259 C260 C261 C262 C264 C265 C266 C268 C269 C270 C274 C298 C302 C329 C330 D22 D26 D29 D31 D32 R11 R18 R20 R31 R32 R104 R130 R210 R211 R212 R213 R219 R221 R224 R225 R227 R229 R286 R287 R288 R289 R290 R291 R292 R293 R294 R298 R299 R301 R302 R303 R304 R305 R306 R311 R316 R317 R318 R319 R320 R321 R322 R323 R324 R325 R326 RT3 U32 U33 U37 U38
component class TIDA-DAB-010054-E4_GateDriverPrimHB1: C78 C154 C155 C156 C157 C158 C159 C160 C161 C162 C163 C164 C165 C166 C167 C168 C169 C170 C171 C172 C173 C174 C175 C176 C177 C178 C179 C180 C181 C182 C183 C184 C185 C186 C187 C188 C189 C190 C191 C192 C325 C326 D14 D15 D17 D20 D24 PWM1 PWM2 PWM3 PWM4 R6 R8 R16 R24 R25 R85 R90 R93 R144 R147 R150 R154 R155 R171 R172 R173 R174 R175 R176 R177 R178 R179 R180 R181 R182 R183 R185 R186 R187 R188 R189 R190 R191 R192 R196 R197 R198 R199 R200 R201 R202 R203 R208 R209 R214 R215 R216 R217 R218 R220 R223 RT1 U14 U24 U26 U29 U30
net class HV: D1H_P MPP MPS NetR64_1 NetR66_1 NetR95_2 NetR96_1 NetR97_2 NetR98_2 NetR101_1 NetR102_2 NetR103_1 NetR105_1 NetR106_1 NetR107_2 NetR108_1 NetR110_2 NetR112_2 NetR124_1 NetR127_1 NetR128_1 NetR145_1 NetR146_1 NetR148_2 NetR149_1 NetR151_1 NetR222_1 NetR281_1 NetR285_1 NetR327_1 NetR359_1 VBATT_N
component class TIDA-DAB-010054-E4_SecondarySideSensing: C79 C80 C81 C82 C83 C84 C85 C86 C87 C89 C90 C91 C92 C93 C97 C98 C99 C100 C101 C102 C103 C104 C105 C106 C107 C108 C109 C110 C111 C114 C239 C263 C267 C271 C323 C333 D11 J37 L7 L8 L9 L10 L11 L12 R13 R22 R23 R37 R40 R64 R87 R88 R89 R91 R92 R95 R96 R97 R98 R100 R101 R102 R103 R105 R106 R107 R108 R109 R110 R111 R114 R115 R116 R117 R118 R123 R125 R126 TP13 TP14 TP15 TP16 TP17 TP24 U2 U9 U10 U12 U13
component class "TIDA-DAB-010054-E4_Power Tree": C62 C63 C64 C65 C66 C67 C68 C69 C70 C71 C72 C74 C75 C76 C77 C314 C? D5 D6 D7 D8 D9 D10 J15 NT1 R68 R69 R70 R71 R72 R73 R74 R75 R76 R77 R78 R80 R81 R83 R84 S1 TP6 TP7 TP10 TP11 U4 U5 U6 U7
component class TIDA-DAB-010054-E4_PowerStage: C15 C16 C19 C20 C21 C22 C23 C24 C25 C26 C28 C30 C31 C32 C33 C34 C35 C36 C37 C38 C39 C40 C41 C42 C43 C44 C45 C46 C47 C48 C49 C50 C51 C52 C53 C54 C55 C56 C57 C58 C59 C60 C61 C138 C145 D1 D2 D3 D4 J11 J12 J13 J14 K1 K3 MP1 MP2 MP3 MP4 MP5 MP6 MP7 MP8 MP9 MP10 MP11 MP12 Q6 Q7 Q8 Q9 Q10 Q11 Q12 Q13 R58 R59 R66 R127 R128 R222 R226 R228 R281 R285 R327 R359 R361 R363 T1 TP1 TP2 TP3 TP4 TP5
component class "TIDA-DAB-010054-E4_Control Card": C1 C2 C3 C4 C5 C6 C7 C8 C9 C10 C11 C12 C13 C14 C73 C96 C121 C122 C136 C137 C313 C319 C320 C321 C322 D13 D16 J1 J2 J3 J4 J5 J6 J8 J9 J10 L1 L2 L3 L4 L5 L6 Q1 Q2 Q3 Q4 R1 R2 R3 R4 R5 R10 R15 R19 R28 R30 R33 R38 R39 R41 R42 R43 R48 R51 R52 R53 R54 R55 R56 R79 R82 R86 R204 R205 TP12 TP20 TP21 TP22 TP23 TP25 TP26 TP27 TP28 TP29 U1 U3 U8
component class "Mounting Holes": H1 H2 H3 H4 H5 H6 H7 H8
component class TIDA-DAB-010054-E4_EVM_Hardware: FID1 FID2 FID3 FID4 FID5 FID6 H1 H2 H3 H4 H5 H6 H7 H8 LBL1 LOGO1 LOGO2 LOGO3 LOGO4 LOGO5 LOGO6 LOGO7 LOGO8 LOGO9 LOGO10 Logo11 Logo12 Logo13 Logo14 Logo15 Logo16 LOGO17 LOGO18 Logo19 MP13 MP14 MP15 MP16 MP17 MP18 MP19 MP20 ZZ1 ZZ2 ZZ3 ZZ4
component class FiducialMark: FID1 FID2 FID3 FID4 FID5 FID6
component class AssemblyNote: ZZ1 ZZ2 ZZ3 ZZ4
component class Label: LBL1
component class Header: J1 J3 J4 J5 J10 J37
pad class mountinghole: H1-1 H2-1 H3-1 H4-1 H5-0 H6-0 H7-0 H8-0 MP13- MP14- MP15- MP16- MP18- MP19- MP20-

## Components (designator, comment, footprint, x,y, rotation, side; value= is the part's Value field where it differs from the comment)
C1 "C0603C103J1RACTU" 0603 16.098,37.805 r90 bottom value=0.01uF
C2 "C3216X7R1E106K160AB" 1206_180L 7.109,141.102 r180 bottom value=10uF
C3 "CL10B105KO8VPNC" 0603 7.522,143.086 r180 bottom value=1uF
C4 "C0603C103J1RACTU" 0603 7.522,144.536 r180 bottom value=0.01uF
C5 "885012206095" 0603 19.533,143.656 r0 bottom value=0.1uF
C6 "C0603C103J1RACTU" 0603 17.796,160.73 r180 bottom value=0.01uF
C7 "CL10B105KO8VPNC" 0603 17.805,159.076 r180 bottom value=1uF
C8 "C3216X7R1E106K160AB" 1206_180L 17.333,162.568 r180 bottom value=10uF
C9 "GRM1885C1H470JA01D" 0603 23.637,160.95 r270 bottom value=47pF
C10 "C0603X472K5RACTU" 0603 26.242,162.5 r180 bottom value=4700pF
C11 "GRM1885C1H470JA01D" 0603 23.637,164.327 r270 bottom value=47pF
C12 "C0603C103J1RACTU" 0603 8.2,158.473 r180 bottom value=0.01uF
C13 "CL10B105KO8VPNC" 0603 8.21,160.162 r180 bottom value=1uF
C14 "C3216X7R1E106K160AB" 1206_180L 7.792,162.068 r180 bottom value=10uF
C15 "C1812V104KDRACTU" 1812_254 245.923,126.863 r180 top value=0.1uF
C16 "C1812V104KDRACTU" 1812_254 64.889,80.664 r270 bottom value=0.1uF
C19 "C1812V104KDRACTU" 1812_254 247.66,73.749 r90 top value=0.1uF
C20 "C1812V104KDRACTU" 1812_254 64.889,80.664 r270 top value=0.1uF
C21 "B32716H8306K000" FP-B32716H8306K000_RADIAL-MFG 221.248,122.87 r180 top value=30µF
C22 "B32716H8306K000" FP-B32716H8306K000_RADIAL-MFG 178.039,122.87 r180 top value=30µF
C23 "B32716H1156K000" FP-B32716H1156K000_RADIAL-MFG 90.907,122.911 r0 top value=15µF
C24 "B32716H1156K000" FP-B32716H1156K000_RADIAL-MFG 134.18,122.87 r0 top value=15µF
C25 "C1812V104KDRACTU" 1812_254 245.923,126.863 r180 bottom value=0.1uF
C26 "C1812V104KDRACTU" 1812_254 66.56,31.199 r0 top value=0.1uF
C28 "C1812V104KDRACTU" 1812_254 247.66,73.749 r90 bottom value=0.1uF
C30 "C1812V104KDRACTU" 1812_254 66.592,31.199 r0 bottom value=0.1uF
C31 "2220Y1K00474KETWS2" 2220 78.87,100.307 r180 bottom value=0.47uF
C32 "CGA9P1X7T2J474M250KC" 2220_280 230.175,100.042 r180 bottom value=0.47uF
C33 "2220Y1K00474KETWS2" 2220 78.87,94.041 r180 bottom value=0.47uF
C34 "CGA9P1X7T2J474M250KC" 2220_280 230.175,93.776 r180 bottom value=0.47uF
C35 "2220Y1K00474KETWS2" 2220 78.87,87.776 r180 bottom value=0.47uF
C36 "CGA9P1X7T2J474M250KC" 2220_280 230.175,87.511 r180 bottom value=0.47uF
C37 "2220Y1K00474KETWS2" 2220 78.87,81.511 r180 bottom value=0.47uF
C38 "CGA9P1X7T2J474M250KC" 2220_280 230.175,81.246 r180 bottom value=0.47uF
C39 "2220Y1K00474KETWS2" 2220 78.87,75.245 r180 bottom value=0.47uF
C40 "CGA9P1X7T2J474M250KC" 2220_280 230.175,74.98 r180 bottom value=0.47uF
C41 "2220Y1K00474KETWS2" 2220 78.87,68.98 r180 bottom value=0.47uF
C42 "CGA9P1X7T2J474M250KC" 2220_280 230.175,68.715 r180 bottom value=0.47uF
C43 "2220Y1K00474KETWS2" 2220 78.87,62.715 r180 bottom value=0.47uF
C44 "CGA9P1X7T2J474M250KC" 2220_280 230.175,62.45 r180 bottom value=0.47uF
C45 "2220Y1K00474KETWS2" 2220 78.87,62.715 r180 top value=0.47uF
C46 "CGA9P1X7T2J474M250KC" 2220_280 230.175,62.45 r180 top value=0.47uF
C47 "2220Y1K00474KETWS2" 2220 78.87,68.98 r180 top value=0.47uF
C48 "CGA9P1X7T2J474M250KC" 2220_280 230.175,68.715 r180 top value=0.47uF
C49 "2220Y1K00474KETWS2" 2220 78.87,75.245 r180 top value=0.47uF
C50 "CGA9P1X7T2J474M250KC" 2220_280 230.175,74.98 r180 top value=0.47uF
C51 "2220Y1K00474KETWS2" 2220 78.87,81.511 r180 top value=0.47uF
C52 "CGA9P1X7T2J474M250KC" 2220_280 230.175,100.042 r180 top value=0.47uF
C53 "2220Y1K00474KETWS2" 2220 78.87,87.776 r180 top value=0.47uF
C54 "CGA9P1X7T2J474M250KC" 2220_280 230.175,93.776 r180 top value=0.47uF
C55 "2220Y1K00474KETWS2" 2220 78.87,94.041 r180 top value=0.47uF
C56 "CGA9P1X7T2J474M250KC" 2220_280 230.175,87.511 r180 top value=0.47uF
C57 "2220Y1K00474KETWS2" 2220 78.87,100.307 r180 top value=0.47uF
C58 "CGA9P1X7T2J474M250KC" 2220_280 230.175,81.246 r180 top value=0.47uF
C59 "CK45-B3FD222KYVNA" CAPRD1000W60D900H1200 139.92,143.68 r180 top value=2200pF
C60 "CK45-B3FD222KYVNA" CAPRD1000W60D900H1200 55,140 r0 top value=2200pF
C61 "CK45-B3FD222KYVNA" CAPRD1000W60D900H1200 269.222,143.437 r0 top value=2200pF
C62 "GCM155R71H104KE02D" 0402S 5.421,124.308 r180 bottom value=0.1uF
C63 "EMK107BB7225KA-T" 0603 3.46,92.617 r90 bottom value=2.2uF
C64 "CL10B104KA8VPJC" FP-CL10B104KA8VPJC_0603-MFG 5.058,92.633 r270 bottom value=100nF
C65 "EMK107BB7225KA-T" 0603 11.452,92.633 r90 bottom value=2.2uF
C66 "C1608X7R1C224K080AC" 0603 11.535,111.647 r0 bottom value=0.22uF
C67 "EMK107BB7225KA-T" 0603 3.406,88.439 r90 bottom value=2.2uF
C68 "CL10B104KA8VPJC" FP-CL10B104KA8VPJC_0603-MFG 5.058,88.439 r270 bottom value=100nF
C69 "EMK107BB7225KA-T" 0603 11.606,88.439 r90 bottom value=2.2uF
C70 "GCM188R71C105KA64D" 0603 4.092,107.605 r0 bottom value=1uF
C71 "GRM32ER71A476KE15L" 1210_270 5.642,97.411 r180 bottom value=47uF
C72 "GRM32ER71A476KE15L" 1210_270 10.865,97.47 r0 bottom value=47uF
C73 "UWT1E101MCL1GS" UWT_630x770 15.977,23.183 r90 top value=100uF
C74 "CL31B106KBHNNNE" 1206_180L 12.067,102.685 r270 bottom value=10uF
C75 "CL31B106KBHNNNE" 1206_180L 4.667,103.137 r270 bottom value=10uF
C76 "GRM1885C1H330JA01D" 0603 7.815,109.602 r0 bottom value=33pF
C77 "C1608X7R1C224K080AC" 0603 4.092,106 r180 bottom value=0.22uF
C78 "CL10B104KA8VPJC" FP-CL10B104KA8VPJC_0603-MFG 45.461,99.95 r90 bottom value=100nF
C79 "CC0603KRX7R7BB225" 0603 260.537,142.298 r270 bottom value=2.2uF
C80 "CL10B104KA8VPJC" FP-CL10B104KA8VPJC_0603-MFG 262.179,142.298 r270 bottom value=100nF
C81 "CL10B104KA8VPJC" FP-CL10B104KA8VPJC_0603-MFG 276.676,144.414 r270 bottom value=100nF
C82 "CC0603KRX7R7BB225" 0603 278.392,144.414 r270 bottom value=2.2uF
C83 "0603ZC100KAT2A" 0603 258.902,144.983 r0 bottom value=10pF
C84 "CL10B105KA8VPJC" FP-CL10B105KA8VPJC_0603-MFG 261.139,135.158 r90 bottom value=1µF
C85 "GCM155R71H104KE02D" 0402L 259.77,134.987 r270 bottom value=0.1uF
C86 "GCM155R71H104KE02D" 0402L 259.77,137.077 r90 bottom value=0.1uF
C87 "CL10B105KA8VPJC" FP-CL10B105KA8VPJC_0603-MFG 261.147,138.464 r270 bottom value=1µF
C88 "CL10B104KA8VPJC" FP-CL10B104KA8VPJC_0603-MFG 264.483,55.018 r180 bottom value=100nF
C89 "0603YC823KAT2A" 0603 261.504,147.472 r90 bottom value=0.082uF
C90 "CL10B105KA8VPJC" FP-CL10B105KA8VPJC_0603-MFG 252.84,135.68 r270 bottom value=1µF
C91 "GCM155R71H104KE02D" 0402L 254.155,135.8 r90 bottom value=0.1uF
C92 "0603ZC100KAT2A" 0603 258.902,149.92 r180 bottom value=10pF
C93 "0603ZC100KAT2A" 0603 11.649,29.796 r180 bottom value=10pF
C94 "CL10B104KA8VPJC" FP-CL10B104KA8VPJC_0603-MFG 45.701,43.097 r90 bottom value=100nF
C95 "CL10B104KA8VPJC" FP-CL10B104KA8VPJC_0603-MFG 265.887,110.439 r270 bottom value=100nF
C96 "UWT1E101MCL1GS" UWT_630x770 284.841,28.683 r90 top value=100uF
C97 "CL10B104KA8VPJC" FP-CL10B104KA8VPJC_0603-MFG 276.56,152.642 r270 bottom value=100nF
C98 "CC0603KRX7R7BB225" 0603 278.291,152.642 r270 bottom value=2.2uF
C99 "CL10B104KA8VPJC" FP-CL10B104KA8VPJC_0603-MFG 276.44,161.157 r270 bottom value=100nF
C100 "CC0603KRX7R7BB225" 0603 278.171,161.157 r270 bottom value=2.2uF
C101 "CC0603KRX7R7BB225" 0603 261.642,152.994 r270 bottom value=2.2uF
C102 "CL10B104KA8VPJC" FP-CL10B104KA8VPJC_0603-MFG 259.976,152.994 r270 bottom value=100nF
C103 "CC0603KRX7R7BB225" 0603 259.976,161.683 r270 bottom value=2.2uF
C104 "CL10B104KA8VPJC" FP-CL10B104KA8VPJC_0603-MFG 261.642,161.683 r270 bottom value=100nF
C105 "C0603C820K5GACTU" 0603 261.642,164.956 r90 bottom value=82pF
C106 "C0603C820K5GACTU" 0603 261.642,156.252 r90 bottom value=82pF
C107 "0603ZC100KAT2A" 0603 5.956,34.671 r180 bottom value=10pF
C108 "0603ZC100KAT2A" 0603 5.966,31.632 r0 bottom value=10pF
C109 "GRM1885C1H221JA01D" 0603 280.596,167.74 r180 bottom value=220pF
C110 "06033C104KAT2A" 0603 219.82,13.62 r180 bottom value=0.1uF
C111 "CL10B105KA8VPJC" FP-CL10B105KA8VPJC_0603-MFG 219.82,11.94 r0 bottom value=1µF
C112 "CGA5L1X7R1H106K160AC" 1206_190L 25.121,55.347 r90 bottom value=10uF
C113 "CGA3E2X7R1H104K080AA" 0603 26.975,54.915 r90 bottom value=0.1uF
C114 "C1608C0G2A392J080AE" 0603 3.867,68.973 r180 bottom value=3900pF
C115 "CL10B105KA8VPJC" FP-CL10B105KA8VPJC_0603-MFG 62.103,129.769 r180 bottom value=1µF
C116 "GCM155R71H104KE02D" 0402L 62.706,131.236 r0 bottom value=0.1uF
C117 "GCM155R71H104KE02D" 0402L 62.293,135.573 r0 bottom value=0.1uF
C118 "CL10B105KA8VPJC" FP-CL10B105KA8VPJC_0603-MFG 61.874,136.982 r180 bottom value=1µF
C119 "CL10B105KA8VPJC" FP-CL10B105KA8VPJC_0603-MFG 58.903,129.769 r180 bottom value=1µF
C120 "GCM155R71H104KE02D" 0402L 59.141,131.218 r0 bottom value=0.1uF
C121 "C0603C100J5GACTU" 0603 17.631,43.747 r0 bottom value=10pF
C122 "C0603C100J5GACTU" 0603 18.227,52.252 r0 bottom value=10pF
C123 "0603ZC100KAT2A" 0603 66.175,158.767 r180 bottom value=10pF
C124 "0603YC823KAT2A" 0603 63.331,156.382 r270 bottom value=0.082uF
C125 "GRM1885C1H332JA01D" 0603 44.613,156.85 r270 bottom value=3300pF
C126 "CL10B104KA8VPJC" FP-CL10B104KA8VPJC_0603-MFG 15.621,70.97 r90 bottom value=100nF
C127 "0603ZC100KAT2A" 0603 66.136,153.962 r0 bottom value=10pF
C128 "GRM188R72E102KW07D" 0603 7.808,74.317 r0 bottom value=1000pF
C129 "CC0603KRX7R7BB225" 0603 62.606,161.14 r90 bottom value=2.2uF
C130 "CGA3E2X7R1E104K080AA" 0603 60.886,161.14 r90 bottom value=0.1uF
C131 "CC0603KRX7R7BB225" 0603 48.229,161.067 r90 bottom value=2.2uF
C132 "CGA3E2X7R1E104K080AA" 0603 49.933,161.081 r90 bottom value=0.1uF
C133 "06035A331JAT2A" 0603 43.74,154.415 r180 bottom value=330pF
C134 "06035A331JAT2A" 0603 44.613,160.1 r90 bottom value=330pF
C135 "GRM188R72A103KA01D" 0603 15.093,81.464 r90 bottom value=0.01uF
C136 "C0603C100J5GACTU" 0603 14.172,43.747 r180 bottom value=10pF
C137 "C0603C100J5GACTU" 0603 14.86,52.252 r180 bottom value=10pF
C138 "UWT1E101MCL1GS" UWT_630x770 276.99,173.353 r270 top value=100uF
C139 "GRM188R72E102KW07D" 0603 63.1,146.827 r270 bottom value=1000pF
C140 "C1608C0G2A392J080AE" 0603 9.264,68.479 r180 bottom value=3900pF
C141 "CGA3E2X7R1E104K080AA" 0603 48.106,150.485 r90 bottom value=0.1uF
C142 "CC0603KRX7R7BB225" 0603 46.479,150.485 r90 bottom value=2.2uF
C143 "CC0603KRX7R7BB225" 0603 63.388,151.588 r90 bottom value=2.2uF
C144 "CGA3E2X7R1E104K080AA" 0603 61.768,151.588 r90 bottom value=0.1uF
C145 "UWT1E101MCL1GS" UWT_630x770 284.14,173.353 r270 top value=100uF
C146 "CL10B104KA8VPJC" FP-CL10B104KA8VPJC_0603-MFG 3.662,84.593 r270 bottom value=100nF
C147 "06033C104KAT2A" 0603 76.425,13.702 r180 bottom value=0.1uF
C148 "CL10B105KA8VPJC" FP-CL10B105KA8VPJC_0603-MFG 76.425,12.024 r0 bottom value=1µF
C149 "CGA5L1X7R1H106K160AC" 1206_190L 25.112,26.386 r90 bottom value=10uF
C150 "CGA3E2X7R1H104K080AA" 0603 27.073,25.854 r90 bottom value=0.1uF
C151 "CL10B104KA8VPJC" FP-CL10B104KA8VPJC_0603-MFG 10.051,84.693 r90 bottom value=100nF
C152 "C0603H103J3GACTU" 0603 4.394,79.279 r90 bottom value=0.01uF
C153 "C1608C0G2A392J080AE" 0603 3.88,65.131 r180 bottom value=3900pF
C154 "885012206095" 0603 11.391,55.414 r0 bottom value=0.1uF
C155 "CGA5L1X7R1H106K160AC" 1206_190L 24.74,83.82 r90 bottom value=10uF
C156 "CGA3E2X7R1H104K080AA" 0603 26.848,83.363 r90 bottom value=0.1uF
C157 "CGA5L1X7R1H106K160AC" 1206_190L 24.936,111.747 r90 bottom value=10uF
C158 "CGA3E2X7R1H104K080AA" 0603 26.83,111.302 r90 bottom value=0.1uF
C159 "CGA3E2X7R1H104K080AA" 0603 25.883,78.181 r270 bottom value=0.1uF
C160 "CGA3E2X7R1H104K080AA" 0603 24.288,105.662 r270 bottom value=0.1uF
C161 "C0603C331K5RACTU" 0603 40.643,77.468 r270 bottom value=330pF
C162 "C0603C331K5RACTU" 0603 43.81,77.468 r270 bottom value=330pF
C163 "C0603C331K5RACTU" 0603 40.595,105.574 r270 bottom value=330pF
C164 "C0603C331K5RACTU" 0603 43.807,105.574 r270 bottom value=330pF
C165 "CGA3E2X7R1H104K080AA" 0603 40.98,84.425 r90 bottom value=0.1uF
C166 "C3216X7R1H225K160AB" 1206_180L 42.998,84.763 r90 bottom value=2.2uF
C167 "CGA3E2X7R1H104K080AA" 0603 40.98,112.731 r90 bottom value=0.1uF
C168 "C3216X7R1H225K160AB" 1206_180L 42.894,113.136 r90 bottom value=2.2uF
C169 "C1206C104K5RACTU" 1206L 46.333,88.981 r0 bottom value=0.1uF
C170 "C3216X5R1H335K160AB" 1206_180L 46.323,86.762 r0 bottom value=3.3uF
C171 "C1206C104K5RACTU" 1206L 45.998,117.639 r0 bottom value=0.1uF
C172 "C3216X5R1H335K160AB" 1206_180L 45.998,115.406 r0 bottom value=3.3uF
C173 "C1206C104K5RACTU" 1206L 41.758,92.135 r90 bottom value=0.1uF
C174 "C3216X7R2A105K160AA" 1206_180L 43.936,92.135 r90 bottom value=1uF
C175 "C0603C101F5GACTU" 0603 25.856,90.716 r180 bottom value=100pF
C176 "C1206C104K5RACTU" 1206L 41.692,120.915 r90 bottom value=0.1uF
C177 "C3216X7R2A105K160AA" 1206_180L 43.817,120.915 r90 bottom value=1uF
C178 "C1206C104K5RACTU" 1206L 41.769,96.274 r270 bottom value=0.1uF
C179 "C3216X7R1H474K160AA" 1206_180L 43.926,96.267 r270 bottom value=0.47uF
C180 "C0603C101F5GACTU" 0603 25.744,119.377 r180 bottom value=100pF
C181 "C1206C104K5RACTU" 1206L 41.692,125.067 r270 bottom value=0.1uF
C182 "C3216X7R1H474K160AA" 1206_180L 43.809,125.067 r270 bottom value=0.47uF
C183 "C0603C101F5GACTU" 0603 25.859,95.71 r180 bottom value=100pF
C184 "C0603C101F5GACTU" 0603 25.744,124.206 r180 bottom value=100pF
C185 "C0603C101F5GACTU" 0603 21.605,100.084 r90 bottom value=100pF
C186 "CL10B105KL9VPJC" FP-CL10B105KL9VPJC_0603-MFG 25.134,99.927 r270 bottom value=1µF
C187 "0603ZC104KAT2A" 0603 26.83,99.945 r270 bottom value=0.1uF
C188 "C0603C331K5RACTU" 0603 41.488,99.95 r270 bottom value=330pF
C189 "C0603C331K5RACTU" 0603 41.482,128.797 r270 bottom value=330pF
C190 "C0603C101F5GACTU" 0603 21.6,128.429 r90 bottom value=100pF
C191 "CL10B105KL9VPJC" FP-CL10B105KL9VPJC_0603-MFG 25.411,128.322 r270 bottom value=1µF
C192 "0603ZC104KAT2A" 0603 27.079,128.322 r270 bottom value=0.1uF
C193 "GRM1885C1H332JA01D" 0603 44.656,147.038 r270 bottom value=3300pF
C194 "06035A331JAT2A" 0603 45.529,144.556 r0 bottom value=330pF
C195 "06035A331JAT2A" 0603 42.112,149.81 r180 bottom value=330pF
C196 "C1206C104K5RACTU" 1206L 265.677,67.924 r180 bottom value=0.1uF
C197 "885012206095" 0603 14.749,4.634 r180 bottom value=0.1uF
C198 "CGA5L1X7R1H106K160AC" 1206_190L 286.4,71.387 r270 bottom value=10uF
C199 "CGA3E2X7R1H104K080AA" 0603 284.419,71.834 r270 bottom value=0.1uF
C200 "CGA5L1X7R1H106K160AC" 1206_190L 286.45,42.984 r270 bottom value=10uF
C201 "CGA3E2X7R1H104K080AA" 0603 284.494,43.322 r270 bottom value=0.1uF
C202 "CGA3E2X7R1H104K080AA" 0603 286.79,77.332 r90 bottom value=0.1uF
C203 "CGA3E2X7R1H104K080AA" 0603 286.805,48.616 r90 bottom value=0.1uF
C204 "C0603C331K5RACTU" 0603 270.72,77.482 r90 bottom value=330pF
C205 "C0603C331K5RACTU" 0603 267.651,77.482 r90 bottom value=330pF
C206 "C0603C331K5RACTU" 0603 270.702,49.007 r90 bottom value=330pF
C207 "C0603C331K5RACTU" 0603 267.505,49.007 r90 bottom value=330pF
C208 "CGA3E2X7R1H104K080AA" 0603 270.686,70.513 r270 bottom value=0.1uF
C209 "C3216X7R1H225K160AB" 1206_180L 268.855,70.077 r270 bottom value=2.2uF
C210 "CGA3E2X7R1H104K080AA" 0603 270.463,41.864 r270 bottom value=0.1uF
C211 "C3216X7R1H225K160AB" 1206_180L 268.588,41.429 r270 bottom value=2.2uF
C212 "C3216X5R1H335K160AB" 1206_180L 265.677,65.596 r180 bottom value=3.3uF
C213 "C1206C104K5RACTU" 1206L 265.32,36.98 r180 bottom value=0.1uF
C214 "C3216X5R1H335K160AB" 1206_180L 265.351,39.095 r180 bottom value=3.3uF
C215 "C1206C104K5RACTU" 1206L 269.563,62.396 r270 bottom value=0.1uF
C216 "C3216X7R2A105K160AA" 1206_180L 267.446,62.396 r270 bottom value=1uF
C217 "C0603C101F5GACTU" 0603 285.285,63.85 r0 bottom value=100pF
C218 "C1206C104K5RACTU" 1206L 269.816,33.791 r270 bottom value=0.1uF
C219 "C3216X7R2A105K160AA" 1206_180L 267.556,33.8 r270 bottom value=1uF
C220 "C1206C104K5RACTU" 1206L 269.563,58.259 r90 bottom value=0.1uF
C221 "C3216X7R1H474K160AA" 1206_180L 267.446,58.259 r90 bottom value=0.47uF
C222 "C0603C101F5GACTU" 0603 285.325,35.211 r0 bottom value=100pF
C223 "C1206C104K5RACTU" 1206L 270.227,29.642 r90 bottom value=0.1uF
C224 "C3216X7R1H474K160AA" 1206_180L 268.113,29.642 r90 bottom value=0.47uF
C225 "C0603C101F5GACTU" 0603 285.285,58.917 r0 bottom value=100pF
C226 "C0603C101F5GACTU" 0603 285.325,30.354 r0 bottom value=100pF
C227 "C0603C101F5GACTU" 0603 288.73,54.774 r270 bottom value=100pF
C228 "CL10B105KL9VPJC" FP-CL10B105KL9VPJC_0603-MFG 286.2,54.774 r90 bottom value=1µF
C229 "0603ZC104KAT2A" 0603 284.525,54.774 r90 bottom value=0.1uF
C230 "C0603C331K5RACTU" 0603 269.816,54.543 r90 bottom value=330pF
C231 "C0603C101F5GACTU" 0603 288.955,25.983 r270 bottom value=100pF
C232 "CGA3E2X7R1H104K080AA" 0603 26.086,50.482 r270 bottom value=0.1uF
C233 "CL10B105KL9VPJC" FP-CL10B105KL9VPJC_0603-MFG 286.199,25.983 r90 bottom value=1µF
C234 "0603ZC104KAT2A" 0603 284.493,25.983 r90 bottom value=0.1uF
C235 "C0603C331K5RACTU" 0603 269.738,25.896 r90 bottom value=330pF
C236 "CGA3E2X7R1H104K080AA" 0603 26.162,20.968 r270 bottom value=0.1uF
C237 "CGA5L1X7R1H106K160AC" 1206_190L 286.488,99.462 r270 bottom value=10uF
C238 "CGA3E2X7R1H104K080AA" 0603 284.432,99.8 r270 bottom value=0.1uF
C239 "0603ZC100KAT2A" 0603 257.398,154.702 r180 bottom value=10pF
C240 "C0603C331K5RACTU" 0603 40.725,49.097 r270 bottom value=330pF
C241 "C0603C331K5RACTU" 0603 43.954,49.097 r270 bottom value=330pF
C242 "C0603C331K5RACTU" 0603 40.711,19.923 r270 bottom value=330pF
C243 "C0603C331K5RACTU" 0603 43.947,19.923 r270 bottom value=330pF
C244 "CGA3E2X7R1H104K080AA" 0603 40.881,56.419 r90 bottom value=0.1uF
C245 "C3216X7R1H225K160AB" 1206_180L 42.857,56.857 r90 bottom value=2.2uF
C246 "CGA3E2X7R1H104K080AA" 0603 40.725,27.167 r90 bottom value=0.1uF
C247 "C3216X7R1H225K160AB" 1206_180L 42.657,27.642 r90 bottom value=2.2uF
C248 "C1206C104K5RACTU" 1206L 45.882,32.006 r0 bottom value=0.1uF
C249 "C3216X5R1H335K160AB" 1206_180L 45.866,29.793 r0 bottom value=3.3uF
C250 "C1206C104K5RACTU" 1206L 46.094,61.025 r0 bottom value=0.1uF
C251 "C3216X5R1H335K160AB" 1206_180L 46.066,58.877 r0 bottom value=3.3uF
C252 "C1206C104K5RACTU" 1206L 41.859,35.24 r90 bottom value=0.1uF
C253 "C3216X7R2A105K160AA" 1206_180L 43.966,35.24 r90 bottom value=1uF
C254 "C0603C101F5GACTU" 0603 25.945,34.059 r180 bottom value=100pF
C255 "C1206C104K5RACTU" 1206L 41.839,64.121 r90 bottom value=0.1uF
C256 "C3216X7R2A105K160AA" 1206_180L 43.946,64.121 r90 bottom value=1uF
C257 "C1206C104K5RACTU" 1206L 41.86,39.389 r270 bottom value=0.1uF
C258 "C3216X7R1H474K160AA" 1206_180L 43.967,39.389 r270 bottom value=0.47uF
C259 "C0603C101F5GACTU" 0603 25.897,62.756 r180 bottom value=100pF
C260 "C1206C104K5RACTU" 1206L 41.808,68.237 r270 bottom value=0.1uF
C261 "C3216X7R1H474K160AA" 1206_180L 43.915,68.237 r270 bottom value=0.47uF
C262 "C0603C101F5GACTU" 0603 25.945,38.914 r180 bottom value=100pF
C263 "0603ZC100KAT2A" 0603 257.398,162.875 r180 bottom value=10pF
C264 "C0603C101F5GACTU" 0603 25.897,67.704 r180 bottom value=100pF
C265 "C0603C101F5GACTU" 0603 22.737,42.947 r90 bottom value=100pF
C266 "CL10B105KL9VPJC" FP-CL10B105KL9VPJC_0603-MFG 25.19,42.947 r270 bottom value=1µF
C267 "0603ZC100KAT2A" 0603 257.596,158.707 r180 bottom value=10pF
C268 "0603ZC104KAT2A" 0603 26.962,42.947 r270 bottom value=0.1uF
C269 "C0603C331K5RACTU" 0603 41.578,43.097 r270 bottom value=330pF
C270 "C0603C101F5GACTU" 0603 22.751,73.588 r90 bottom value=100pF
C271 "0603ZC100KAT2A" 0603 258.427,166.506 r90 bottom value=10pF
C272 "0603ZC100KAT2A" 0603 64.038,149.164 r180 bottom value=10pF
C273 "0603ZC100KAT2A" 0603 64.858,143.548 r270 bottom value=10pF
C274 "CL10B105KL9VPJC" FP-CL10B105KL9VPJC_0603-MFG 25.453,72 r270 bottom value=1µF
C275 "CGA5L1X7R1H106K160AC" 1206_190L 286.588,127.363 r270 bottom value=10uF
C276 "CGA3E2X7R1H104K080AA" 0603 284.607,127.816 r270 bottom value=0.1uF
C277 "CGA3E2X7R1H104K080AA" 0603 286.759,133.309 r90 bottom value=0.1uF
C278 "C0603C331K5RACTU" 0603 270.622,133.631 r90 bottom value=330pF
C279 "C0603C331K5RACTU" 0603 267.37,133.631 r90 bottom value=330pF
C280 "CGA3E2X7R1H104K080AA" 0603 270.451,126.631 r270 bottom value=0.1uF
C281 "C3216X7R1H225K160AB" 1206_180L 268.589,126.388 r270 bottom value=2.2uF
C282 "CGA3E2X7R1H104K080AA" 0603 286.706,105.157 r90 bottom value=0.1uF
C283 "C0603C331K5RACTU" 0603 270.522,104.698 r90 bottom value=330pF
C284 "C0603C331K5RACTU" 0603 266.727,104.75 r90 bottom value=330pF
C285 "CGA3E2X7R1H104K080AA" 0603 270.572,98.49 r270 bottom value=0.1uF
C286 "C3216X7R1H225K160AB" 1206_180L 268.738,97.917 r270 bottom value=2.2uF
C287 "C1206C104K5RACTU" 1206L 267.8,123.232 r180 bottom value=0.1uF
C288 "C3216X5R1H335K160AB" 1206_180L 267.828,121.08 r180 bottom value=3.3uF
C289 "C1206C104K5RACTU" 1206L 265.597,96.956 r180 bottom value=0.1uF
C290 "C3216X5R1H335K160AB" 1206_180L 265.597,94.852 r180 bottom value=3.3uF
C291 "C1206C104K5RACTU" 1206L 269.638,117.94 r270 bottom value=0.1uF
C292 "C3216X7R2A105K160AA" 1206_180L 267.534,117.911 r270 bottom value=1uF
C293 "C0603C101F5GACTU" 0603 285.236,119.763 r0 bottom value=100pF
C294 "C1206C104K5RACTU" 1206L 269.633,90.691 r270 bottom value=0.1uF
C295 "C3216X7R2A105K160AA" 1206_180L 267.518,90.691 r270 bottom value=1uF
C296 "C1206C104K5RACTU" 1206L 269.638,113.811 r90 bottom value=0.1uF
C297 "C3216X7R1H474K160AA" 1206_180L 267.534,113.816 r90 bottom value=0.47uF
C298 "0603ZC104KAT2A" 0603 27.101,72 r270 bottom value=0.1uF
C299 "C0603C101F5GACTU" 0603 285.089,91.65 r0 bottom value=100pF
C300 "C1206C104K5RACTU" 1206L 269.648,86.541 r90 bottom value=0.1uF
C301 "C3216X7R1H474K160AA" 1206_180L 267.535,86.541 r90 bottom value=0.47uF
C302 "C0603C331K5RACTU" 0603 41.608,71.904 r270 bottom value=330pF
C303 "C0603C101F5GACTU" 0603 285.236,114.861 r0 bottom value=100pF
C304 "C0603C101F5GACTU" 0603 285.089,86.793 r0 bottom value=100pF
C305 "C0603C101F5GACTU" 0603 289.036,110.828 r270 bottom value=100pF
C306 "CL10B105KL9VPJC" FP-CL10B105KL9VPJC_0603-MFG 286.287,110.828 r90 bottom value=1µF
C307 "0603ZC104KAT2A" 0603 284.579,110.828 r90 bottom value=0.1uF
C308 "C0603C331K5RACTU" 0603 269.976,110.133 r90 bottom value=330pF
C309 "C0603C101F5GACTU" 0603 289.097,82.735 r270 bottom value=100pF
C310 "CL10B105KL9VPJC" FP-CL10B105KL9VPJC_0603-MFG 286.4,82.735 r90 bottom value=1µF
C311 "0603ZC104KAT2A" 0603 284.706,82.735 r90 bottom value=0.1uF
C312 "C0603C331K5RACTU" 0603 269.791,82.904 r90 bottom value=330pF
C313 "C0603C103J1RACTU" 0603 17.752,46.856 r90 bottom value=0.01uF
C314 "UWT1E101MCL1GS" UWT_630x770 26.275,136.586 r90 top value=100uF
C315 "06035A331JAT2A" 0603 12.056,73.275 r270 bottom value=330pF
C316 "06035A331JAT2A" 0603 13.192,76.853 r0 bottom value=330pF
C317 "06035A331JAT2A" 0603 17.493,74.305 r270 bottom value=330pF
C318 "06035A331JAT2A" 0603 16.516,78.479 r180 bottom value=330pF
C319 "C0603C103J1RACTU" 0603 15.657,40.07 r180 bottom value=0.01uF
C320 "C0603C103J1RACTU" 0603 11,41.769 r90 bottom value=0.01uF
C321 "C0603C103J1RACTU" 0603 14.488,34.889 r0 bottom value=0.01uF
C322 "C0603C103J1RACTU" 0603 10.383,46.856 r90 bottom value=0.01uF
C323 "C1608C0G2A392J080AE" 0603 6.02,42.418 r0 bottom value=3900pF
C324 "C1608C0G2A392J080AE" 0603 6.02,44.094 r0 bottom value=3900pF
C325 "CGA5L1X7R1H106K160AC" 1206_190L 22.581,83.798 r90 bottom value=10uF
C326 "CGA5L1X7R1H106K160AC" 1206_190L 22.708,111.738 r90 bottom value=10uF
C327 "CGA5L1X7R1H106K160AC" 1206_190L 288.747,71.396 r270 bottom value=10uF
C328 "CGA5L1X7R1H106K160AC" 1206_190L 288.773,42.973 r270 bottom value=10uF
C329 "CGA5L1X7R1H106K160AC" 1206_190L 22.962,55.321 r90 bottom value=10uF
C330 "CGA5L1X7R1H106K160AC" 1206_190L 22.911,26.369 r90 bottom value=10uF
C331 "CGA5L1X7R1H106K160AC" 1206_190L 288.857,99.472 r270 bottom value=10uF
C332 "CGA5L1X7R1H106K160AC" 1206_190L 288.9,127.356 r270 bottom value=10uF
C333 "C1608C0G2A392J080AE" 0603 223.088,13.614 r0 bottom value=3900pF
C334 "C1608C0G2A392J080AE" 0603 79.82,13.691 r0 bottom value=3900pF
D1 "BAV21WS-TP" SOD-323 182.984,174.904 r180 bottom value=250V
D2 "1SMA5927BT3G" SMA 176.117,174.904 r0 bottom value=12V
D3 "BAV21WS-TP" SOD-323 237.56,174.88 r180 bottom value=250V
D4 "1SMA5927BT3G" SMA 231.24,174.88 r0 bottom value=12V
D5 "SMBJ36CA" FP-SMBJ36CA_DO-214AA-0 3.46,119.235 r270 bottom
D6 "LTST-C193KRKT-5A" LTST-C193_Red 2.698,118.425 r0 top value=Red
D7 "SMCJ36CA" SMC_Bi 8.776,134.086 r90 bottom value=36V
D8 "150060VS75000" WL-SMCW_GREEN 4.134,112.456 r270 top value=Green
D9 "B250A-13-F" SMA 4.18,113.27 r180 bottom value=50V
D10 "150060VS75000" WL-SMCW_GREEN 11.758,96.435 r180 top value=Green
D11 "150060VS75000" WL-SMCW_GREEN 257.2,134.184 r0 bottom value=Green
D12 "150060VS75000" WL-SMCW_GREEN 59.891,122.794 r270 bottom value=Green
D13 "SBR0560S1-7" SOD-123 11.333,17.559 r90 bottom value=60V
D14 "US1Q-TP" FP-US1Q-TP_SMA-MFG 55.569,87.568 r90 bottom
D15 "US1Q-TP" FP-US1Q-TP_SMA-MFG 56.381,110.085 r90 bottom
D16 "SBR0560S1-7" SOD-123 287.032,20.445 r270 bottom value=60V
D17 "KG DELLS1.22-JGKH-24" "FP-KG DELLS1.22-JGKH-24_0603-MFG" 49.443,116.707 r270 bottom
D18 "US1Q-TP" FP-US1Q-TP_SMA-MFG 257.991,65.85 r270 bottom
D19 "US1Q-TP" FP-US1Q-TP_SMA-MFG 257.063,42.57 r270 bottom
D20 "KG DELLS1.22-JGKH-24" "FP-KG DELLS1.22-JGKH-24_0603-MFG" 49.24,90.727 r270 bottom
D21 "KG DELLS1.22-JGKH-24" "FP-KG DELLS1.22-JGKH-24_0603-MFG" 262.716,65.229 r90 bottom
D22 "US1Q-TP" FP-US1Q-TP_SMA-MFG 56.32,59.31 r90 bottom
D23 "KG DELLS1.22-JGKH-24" "FP-KG DELLS1.22-JGKH-24_0603-MFG" 261.798,42.217 r180 bottom
D24 "US1Q-TP" FP-US1Q-TP_SMA-MFG 45.778,104.024 r90 top
D25 "US1Q-TP" FP-US1Q-TP_SMA-MFG 257.917,116.798 r270 bottom
D26 "US1Q-TP" FP-US1Q-TP_SMA-MFG 55.798,37.188 r90 bottom
D27 "US1Q-TP" FP-US1Q-TP_SMA-MFG 256.745,92.88 r270 bottom
D28 "US1Q-TP" FP-US1Q-TP_SMA-MFG 265.367,50.86 r270 top
D29 "US1Q-TP" FP-US1Q-TP_SMA-MFG 45.773,47.172 r90 top
D30 "US1Q-TP" FP-US1Q-TP_SMA-MFG 265.637,106.3 r270 top
D31 "KG DELLS1.22-JGKH-24" "FP-KG DELLS1.22-JGKH-24_0603-MFG" 48.957,61.633 r270 bottom
D32 "KG DELLS1.22-JGKH-24" "FP-KG DELLS1.22-JGKH-24_0603-MFG" 49.039,33.993 r0 bottom
D33 "KG DELLS1.22-JGKH-24" "FP-KG DELLS1.22-JGKH-24_0603-MFG" 261.703,95.031 r180 bottom
D34 "KG DELLS1.22-JGKH-24" "FP-KG DELLS1.22-JGKH-24_0603-MFG" 263.332,120.063 r270 bottom
FID1 "Fiducial" Fiducial10-20 7.62,163.83 r90 top
FID2 "Fiducial" Fiducial10-20 276.84,22.46 r90 top
FID3 "Fiducial" Fiducial10-20 293.37,166.37 r90 top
